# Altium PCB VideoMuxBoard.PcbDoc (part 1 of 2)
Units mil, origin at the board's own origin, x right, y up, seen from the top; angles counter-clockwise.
Board outline 4724.41 x 4724.41 mil, 4 copper layers (Top Layer, Ground, MidLayer1, Bottom Layer); 247 components, 183 nets, 999 pads, 433 vias.
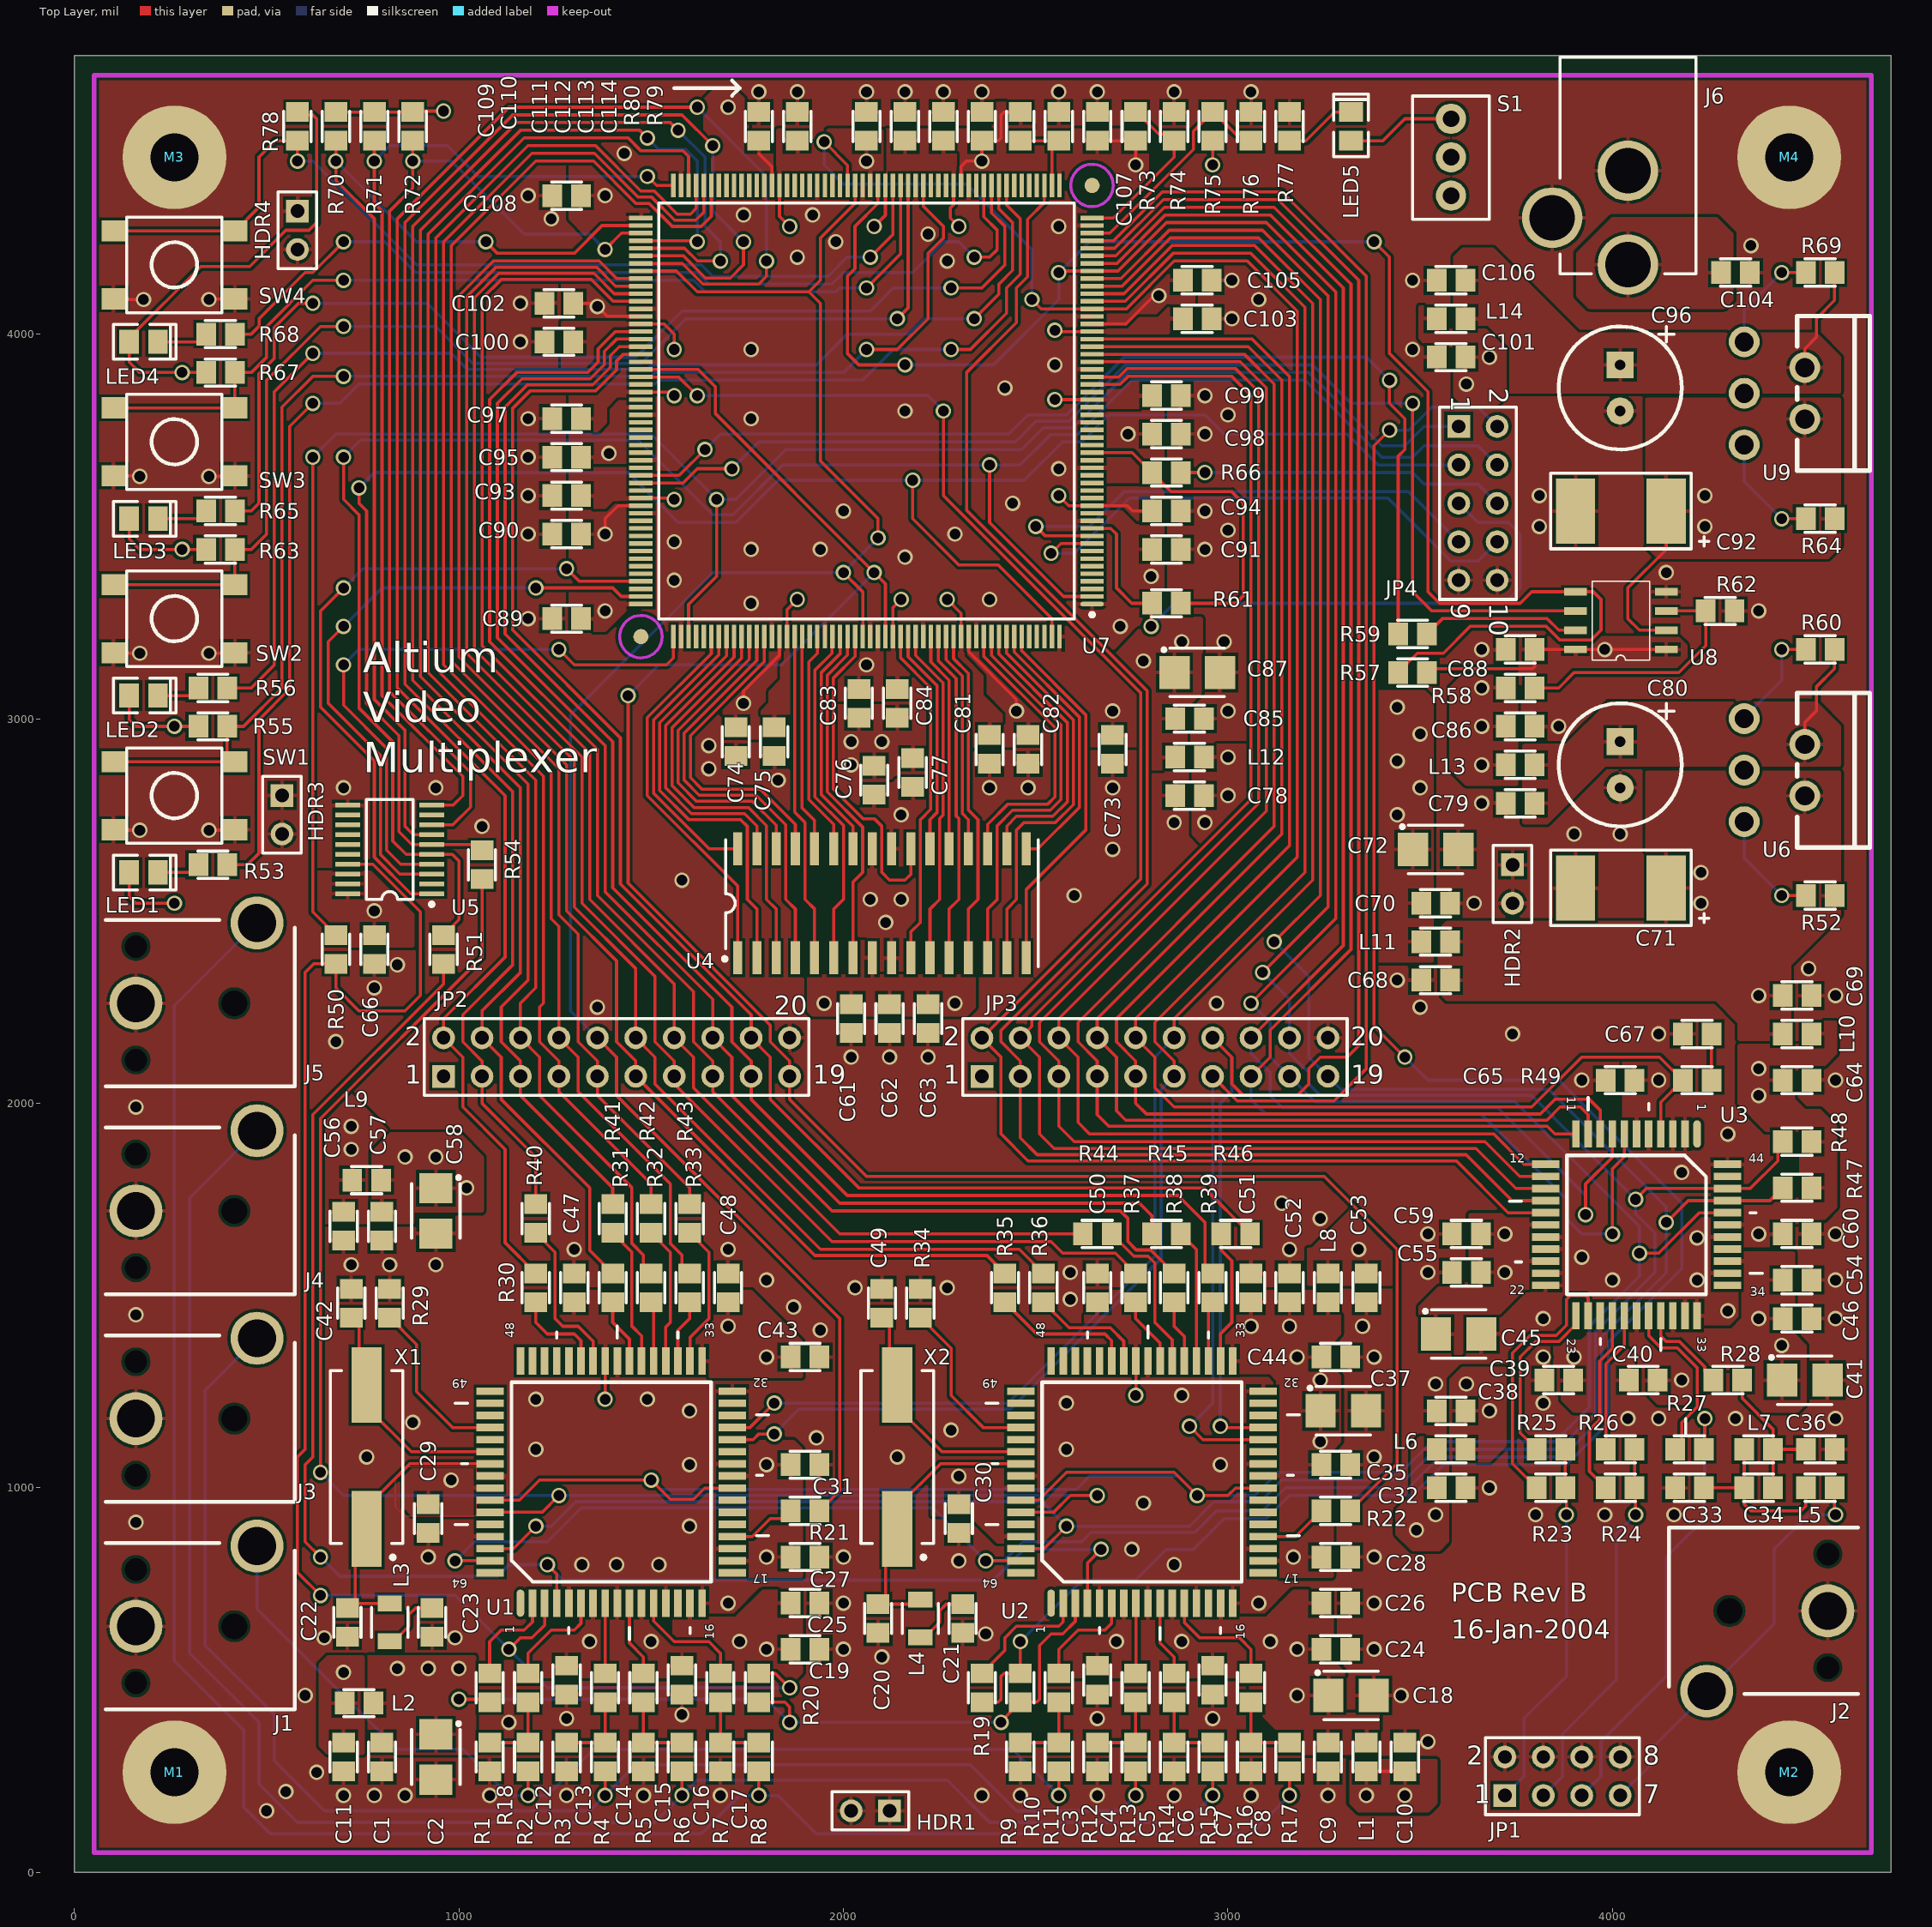
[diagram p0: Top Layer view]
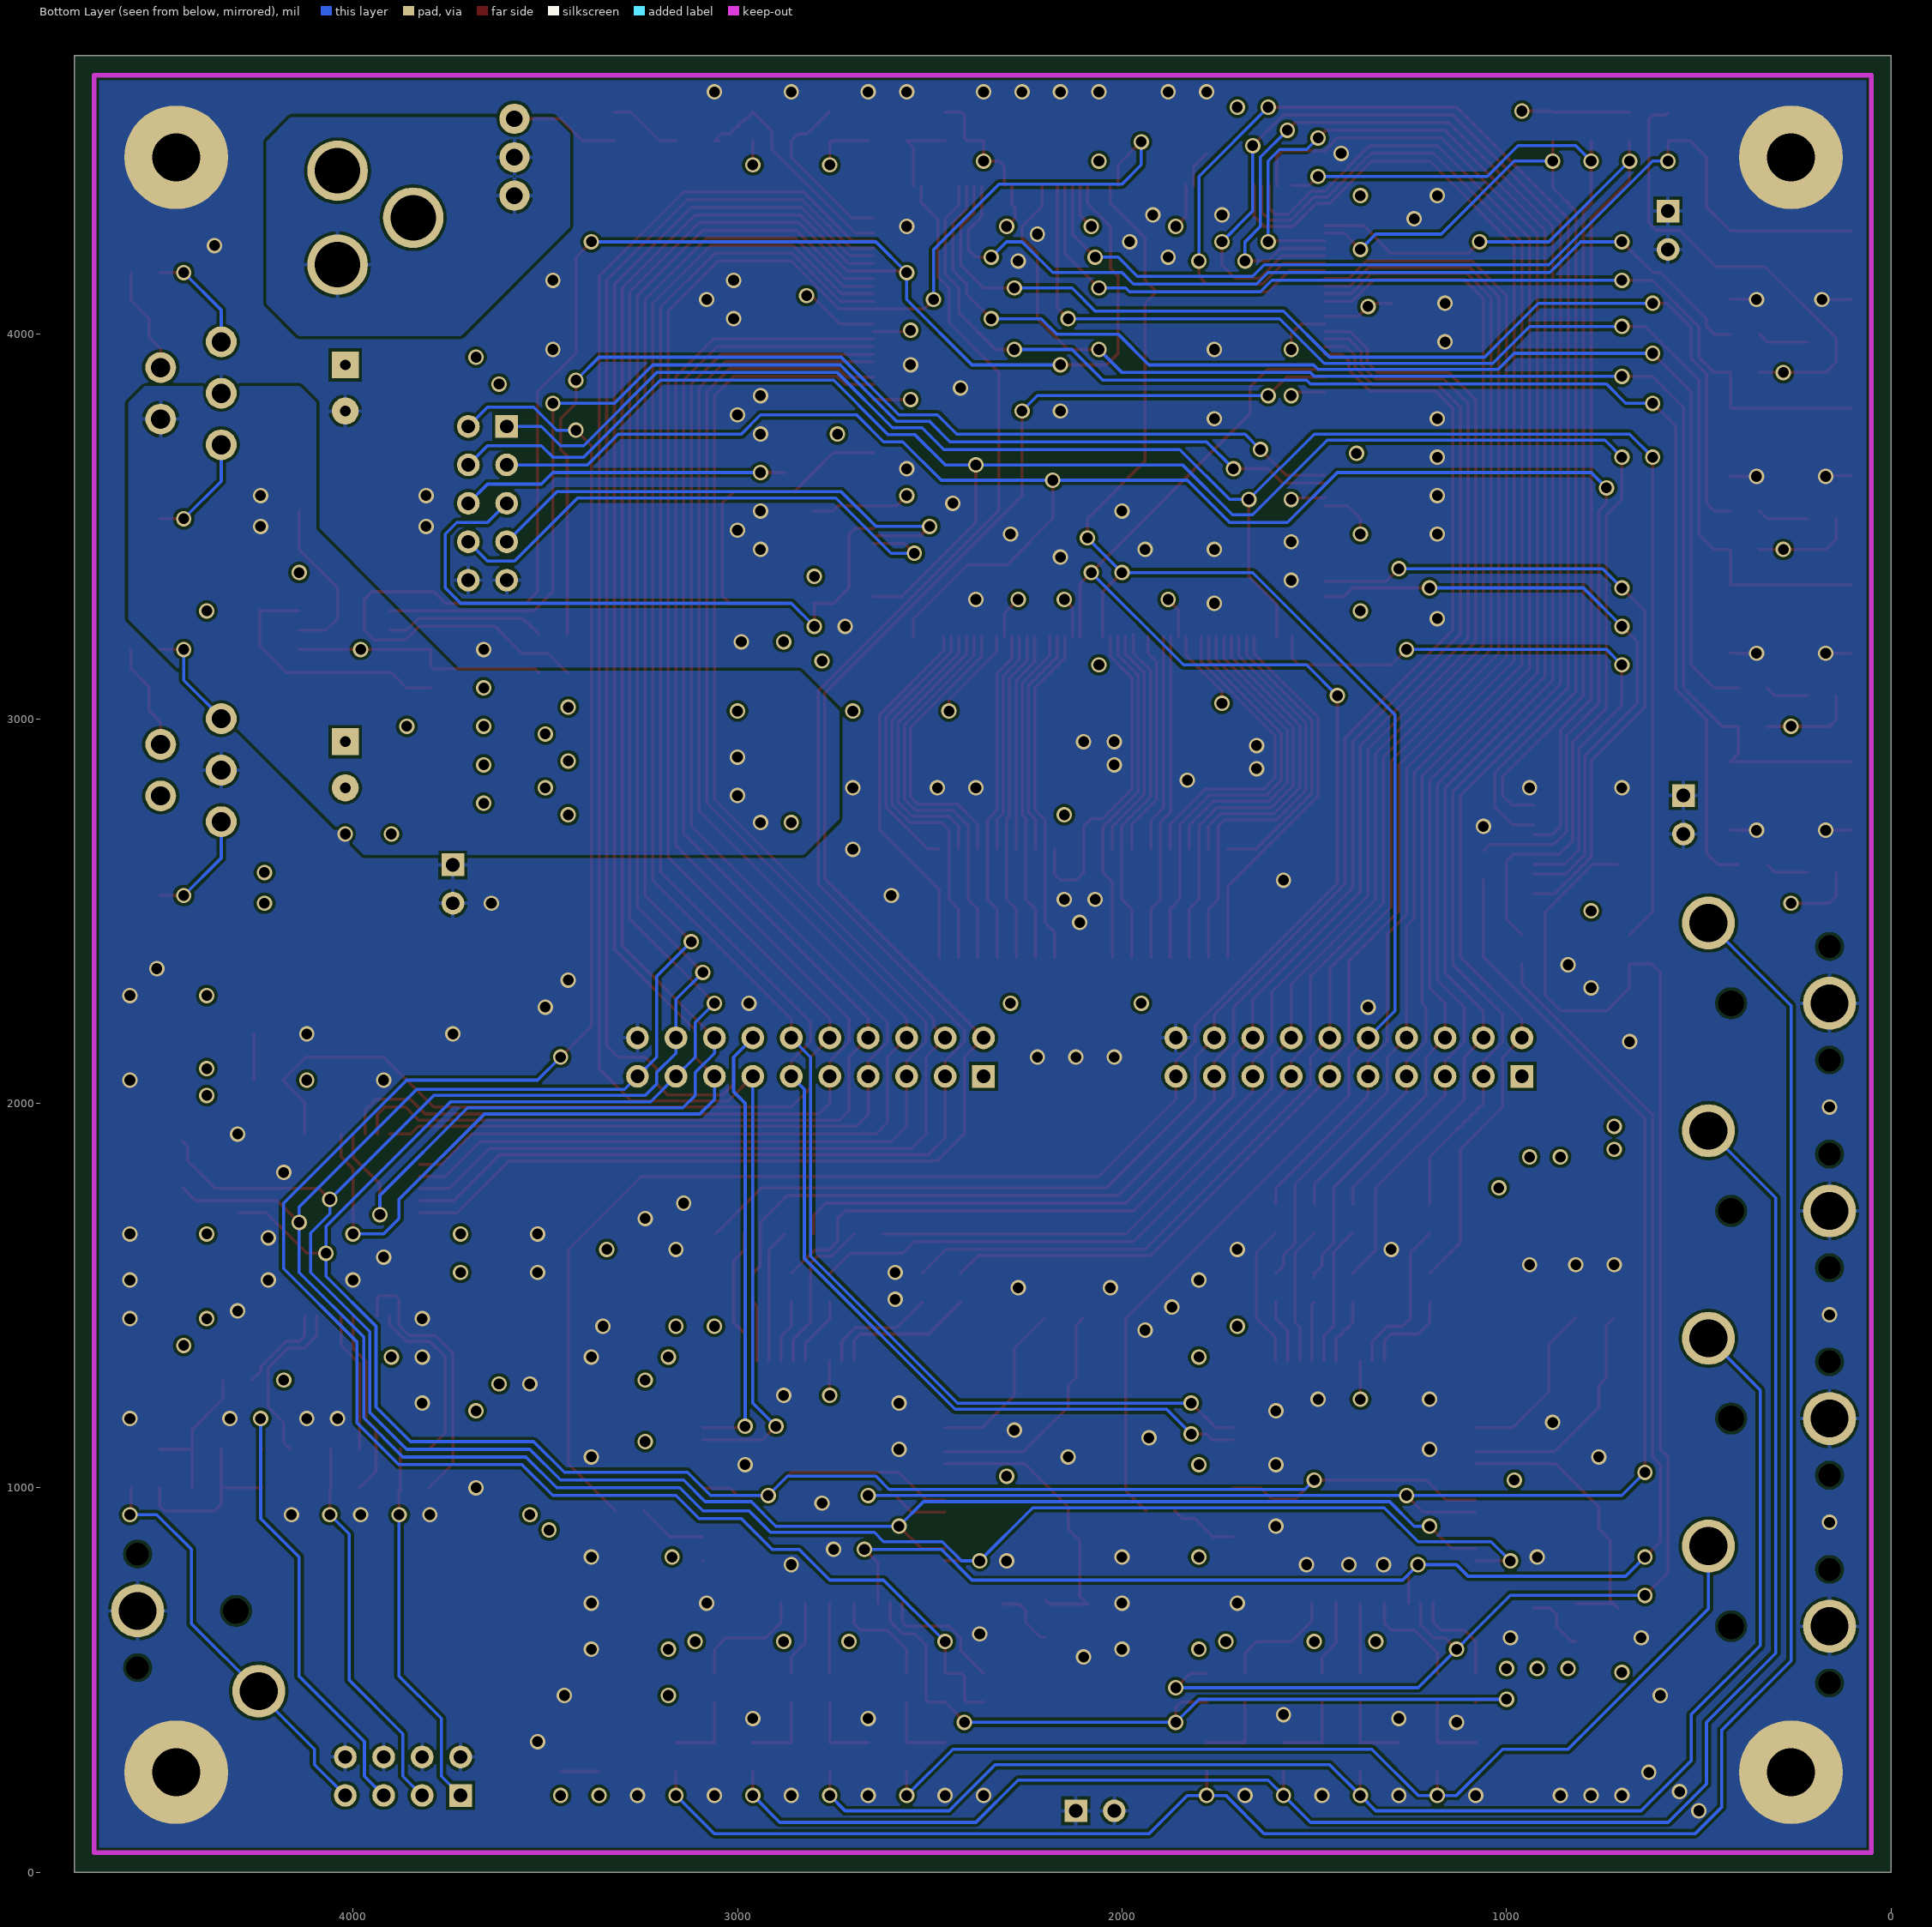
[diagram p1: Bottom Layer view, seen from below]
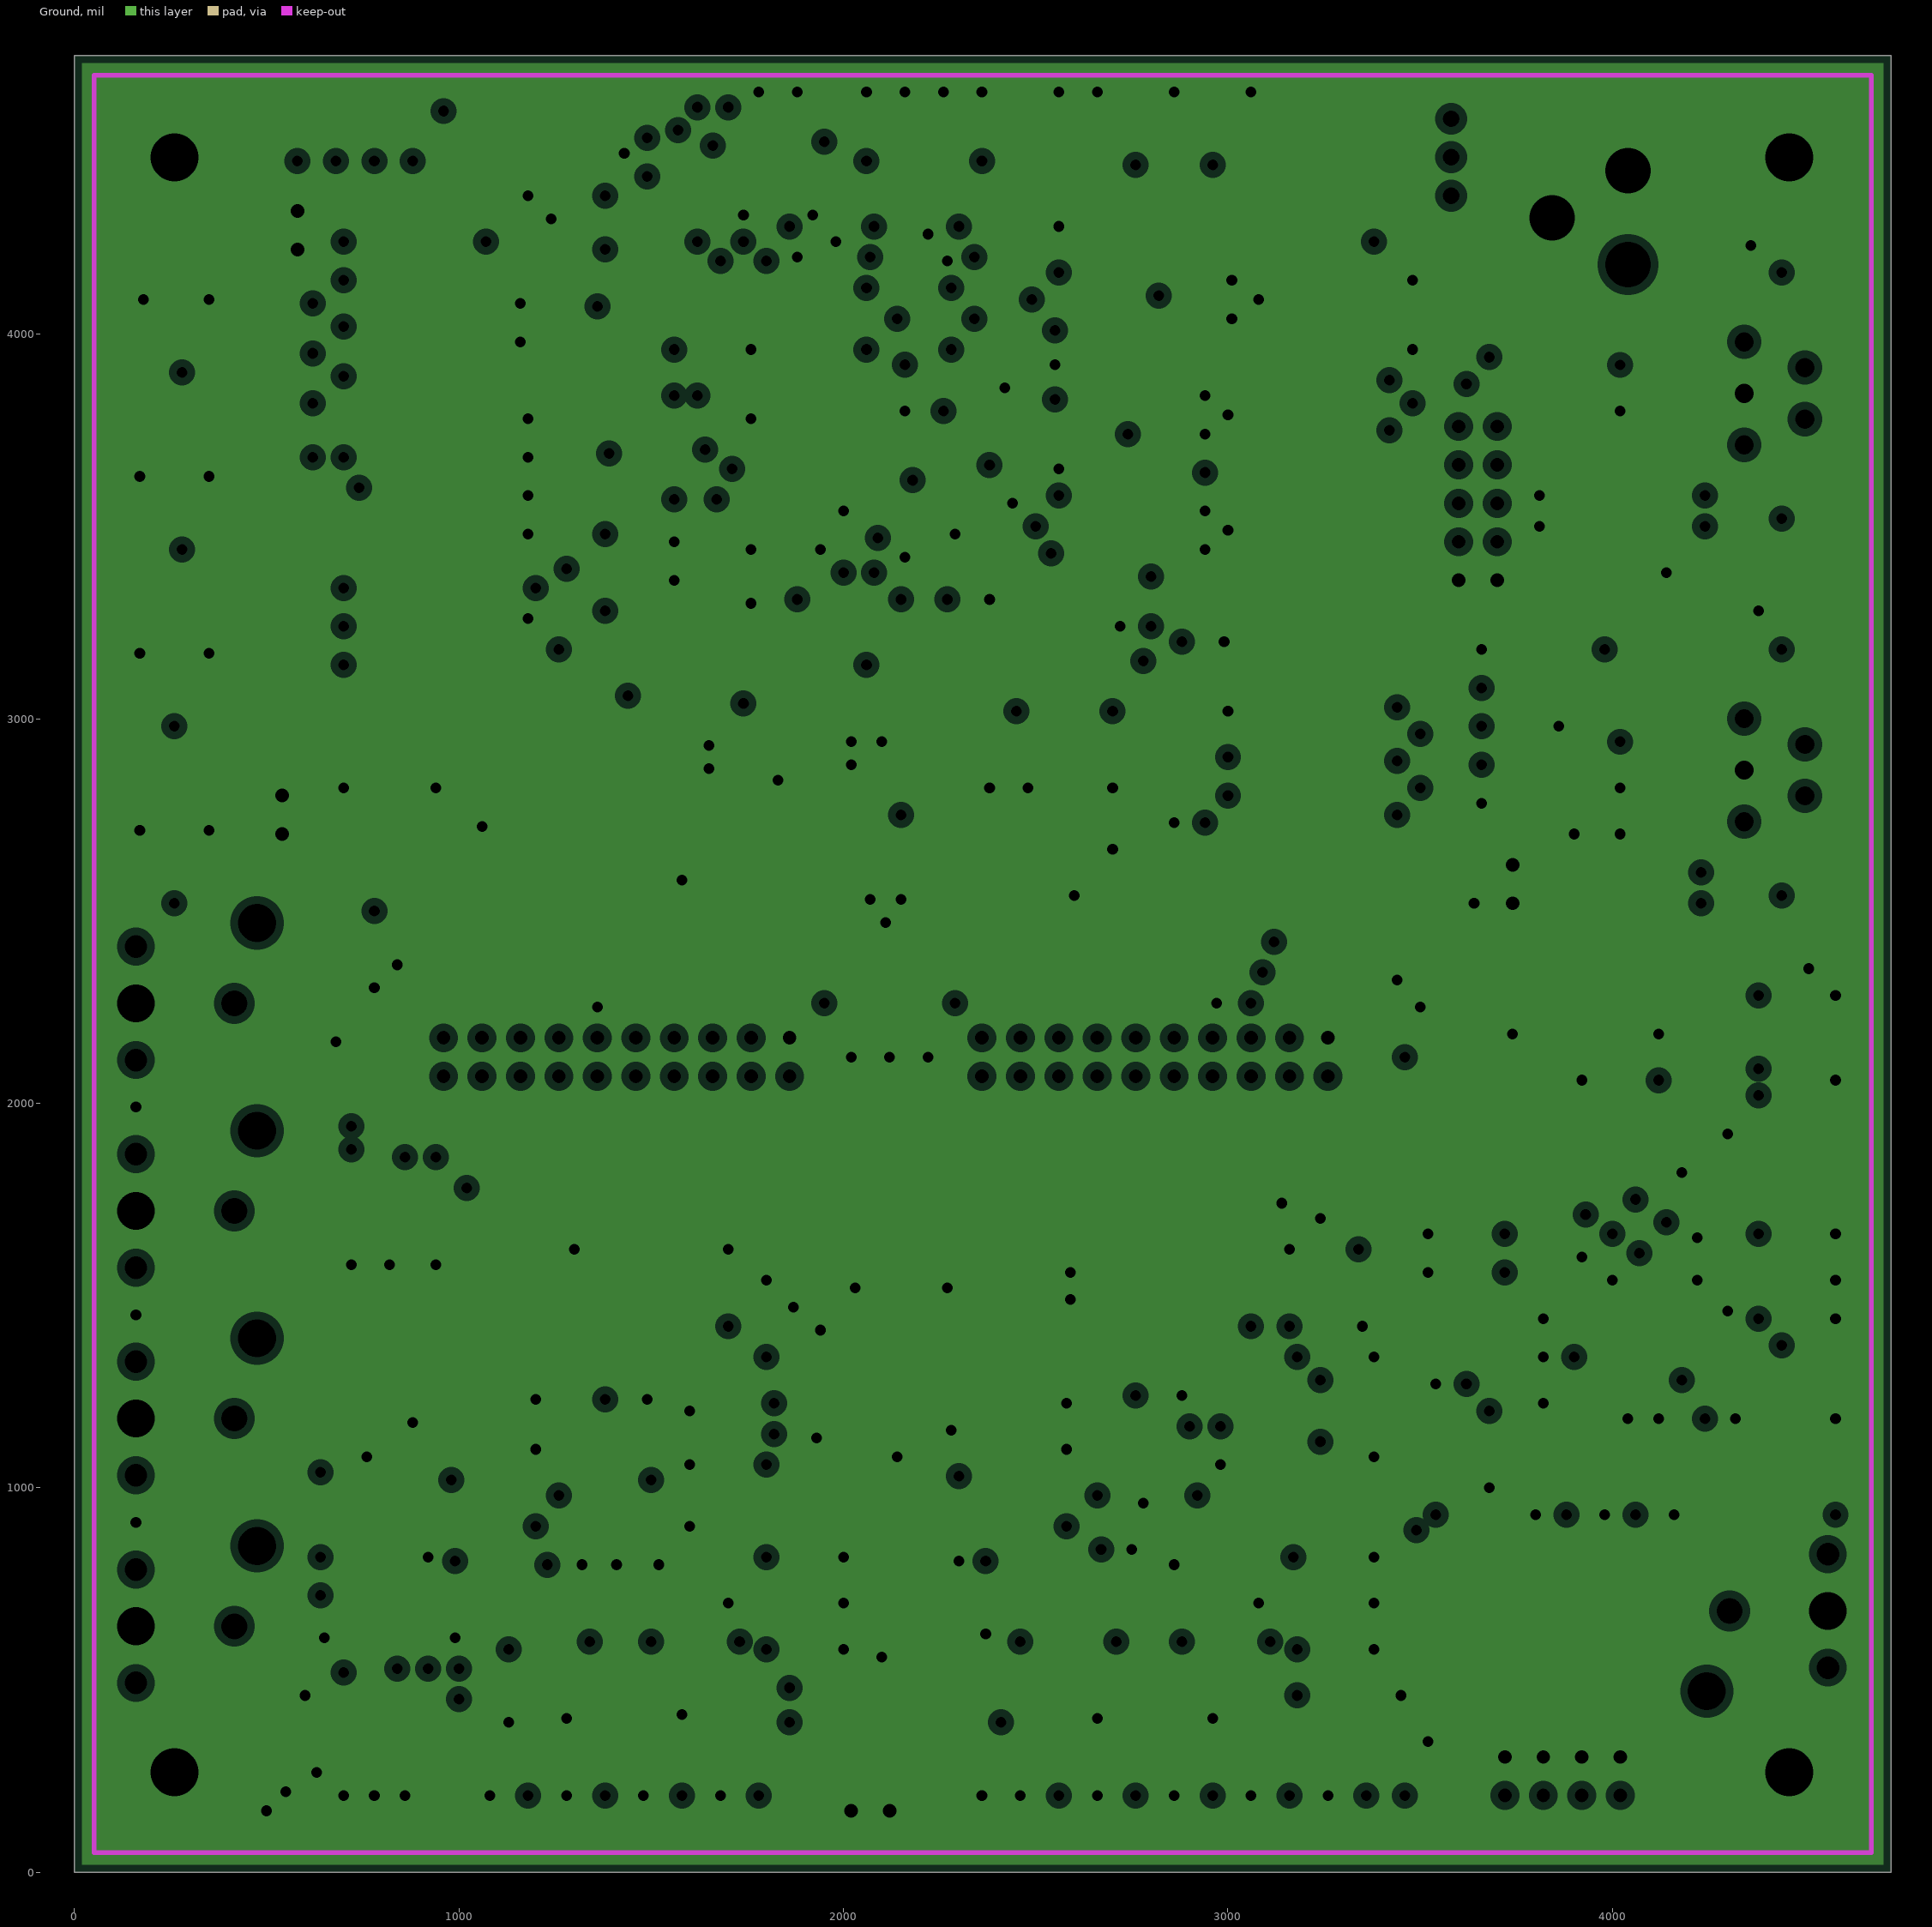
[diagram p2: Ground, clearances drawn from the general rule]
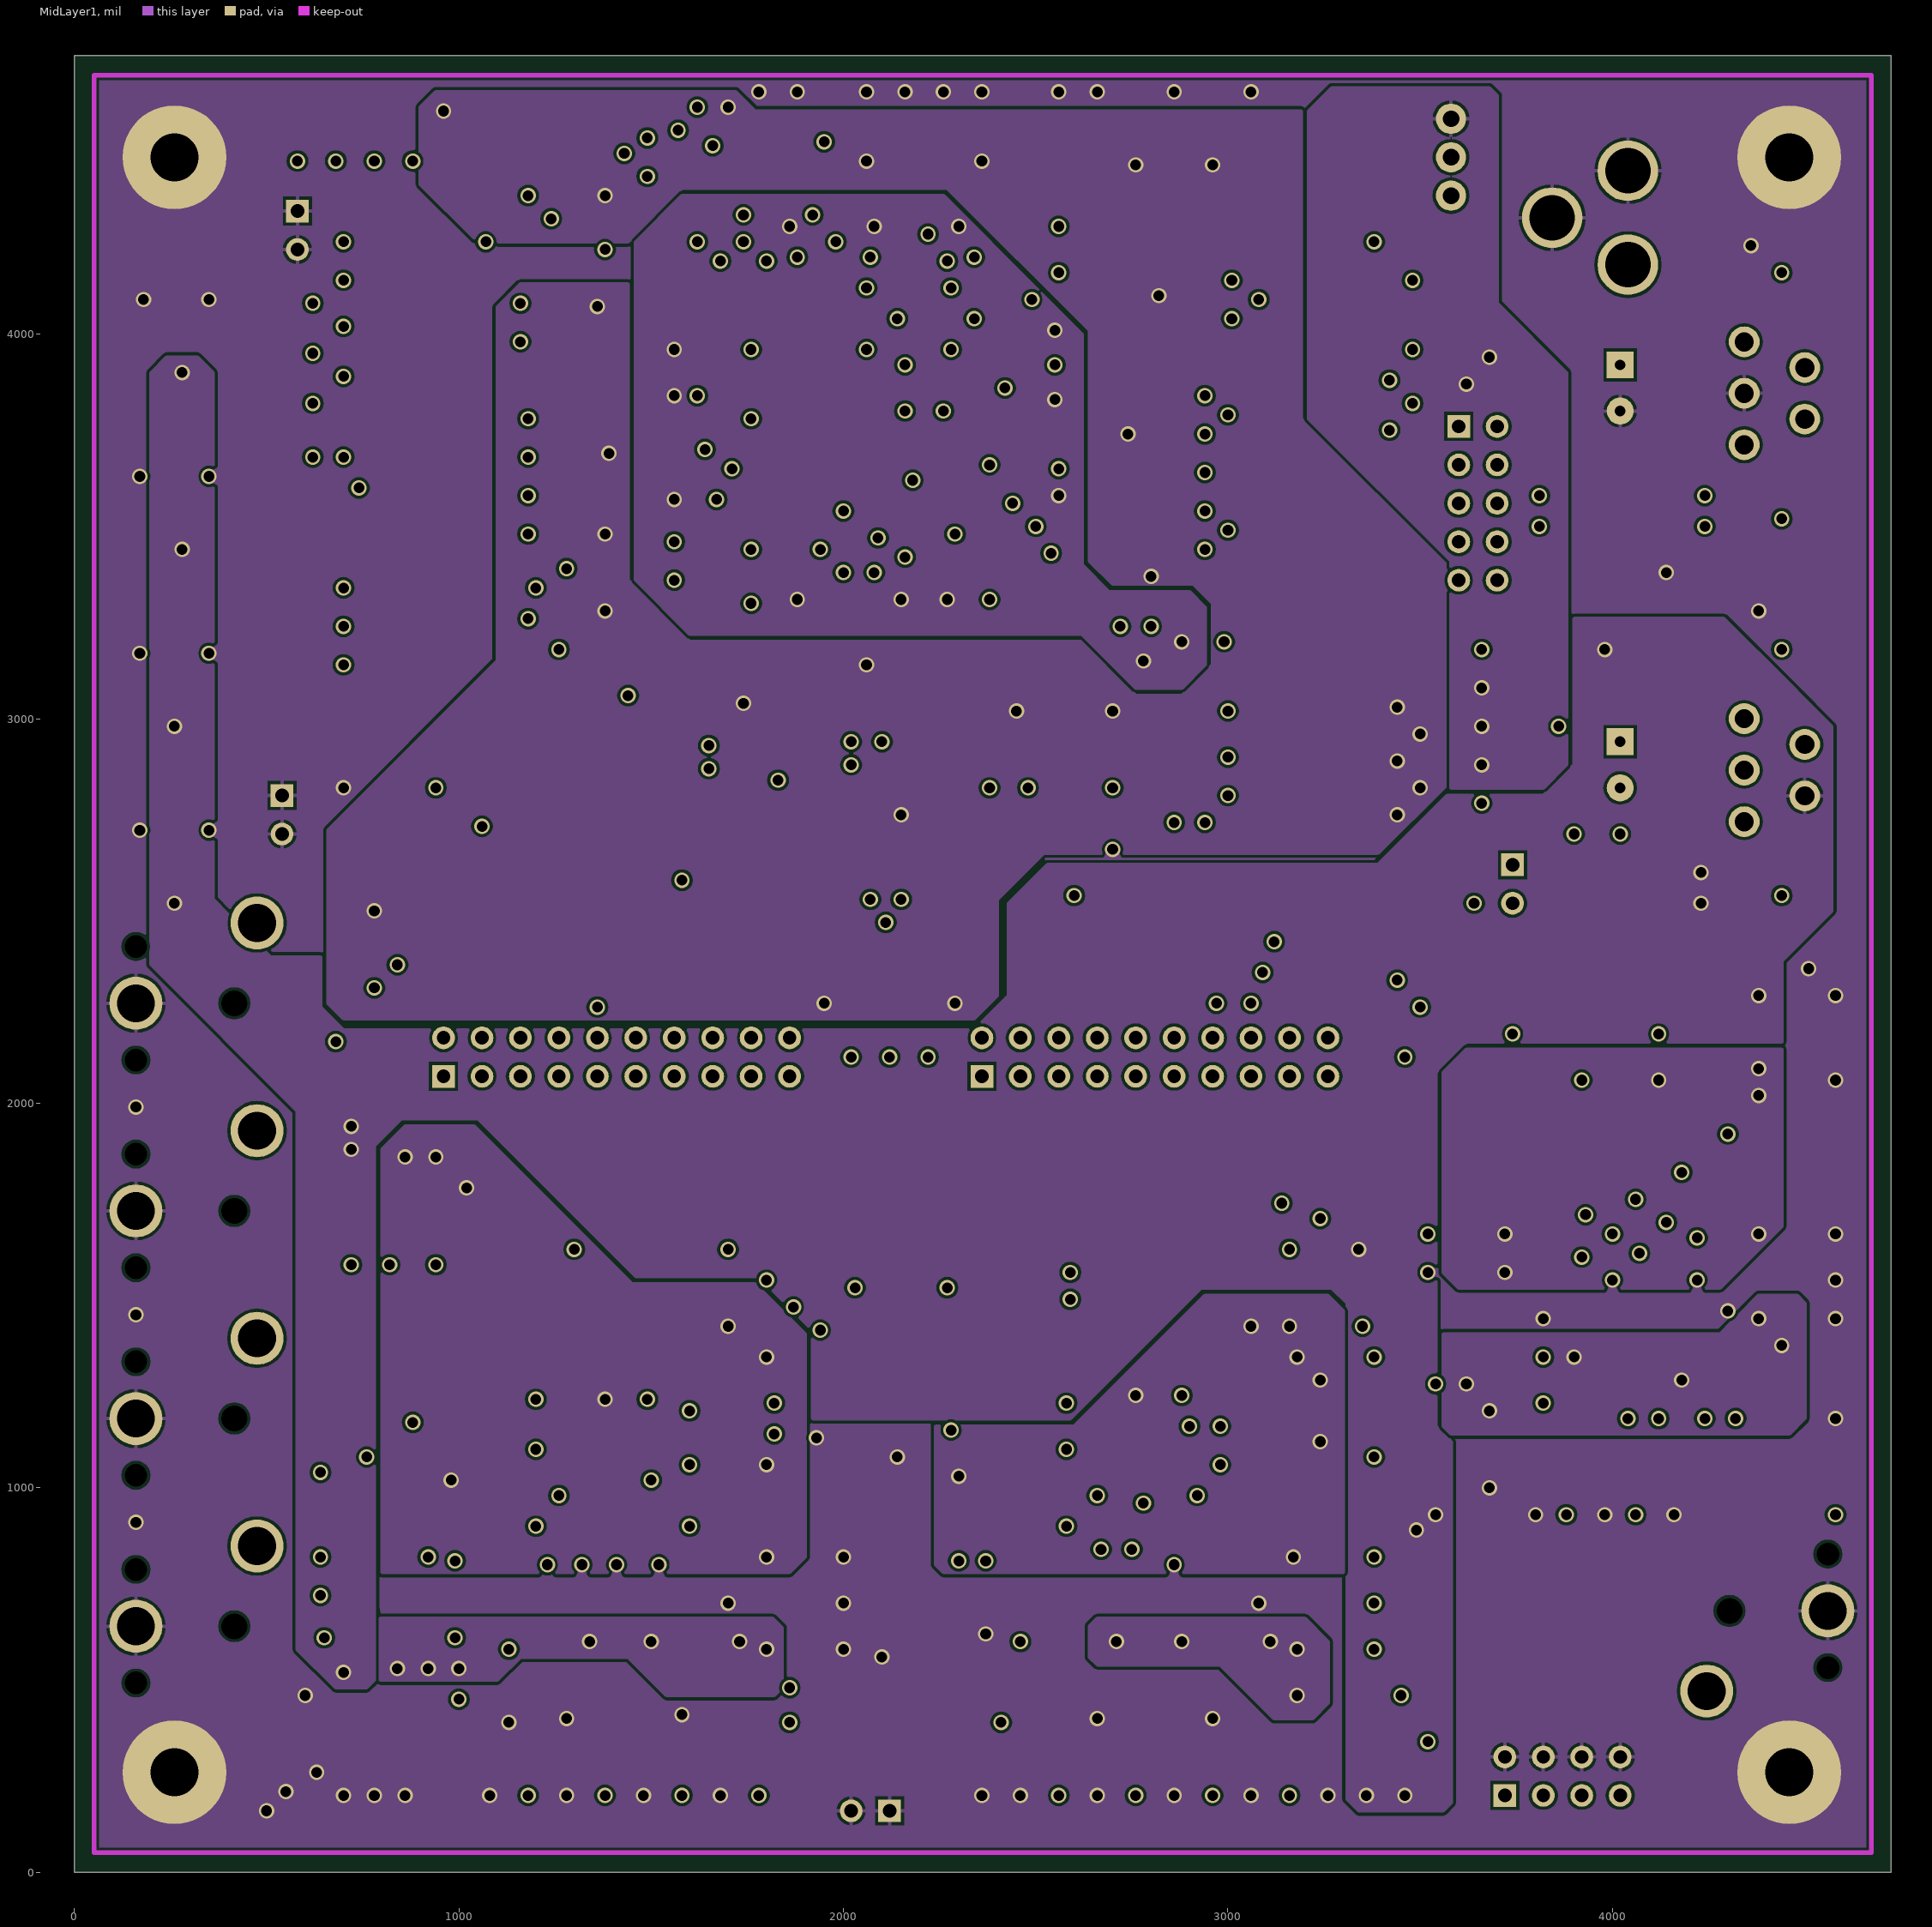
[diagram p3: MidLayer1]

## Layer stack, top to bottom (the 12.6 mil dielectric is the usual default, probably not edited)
Top Layer: signal copper 1.4
Dielectric: core 12.6, FR-4, Dk 4.8
Ground: plane copper 1.4, net GND
Dielectric: prepreg 12.6, FR-4, Dk 4.8
MidLayer1: signal copper 1.4
Dielectric: core 12.6, FR-4, Dk 4.8
Bottom Layer: signal copper 1.4

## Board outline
0,0 4724.41,0 4724.41,4724.41 0,4724.41

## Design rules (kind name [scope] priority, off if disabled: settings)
Clearance [All] p1: gap=7.87
FabricationTestPointUsage TestPointUsage [All] p1: valid=0 allowmultiple=FALSE
FabricationTestpoint Testpoint [All] p1: side=3 testpointundercomponent=TRUE minsize=40 maxsize=100 preferedsize=60 minholesize=0 maxholesize=40 preferedholesize=32 testpointgrid=1 allowsidetop=TRUE allowsidebottom=TRUE usegrid=TRUE gridtolerance=0.01
HoleSize [All] p1: absolutevalues=TRUE maxlimit=150 minlimit=24 maxpercent=80.000 minpercent=20.000
PlaneClearance [All] p1: clearance=20
PlaneConnect M3PlaneConnect [(HasFootprint('SCREW M3') AND InNet('GND'))] p1: planeconnectstyle=Direct reliefexpansion=20 reliefentries=4 reliefconductorwidth=10 reliefairgap=10 // Require no thermal relief on M3 screw holes.
PlaneConnect [All] p2: planeconnectstyle=Relief reliefexpansion=20 reliefentries=4 reliefconductorwidth=10 reliefairgap=10
PolygonConnect M3PolygonConnect [(HasFootprint('SCREW M3') AND InNet('GND'))] p1: connectstyle=Direct reliefconductorwidth=10 reliefentries=4 polygonreliefangle="90 Angle" // Require no thermal relief on M3 screw holes.
PolygonConnect [All] p2: connectstyle=Relief reliefconductorwidth=10 reliefentries=4 polygonreliefangle="90 Angle"
RoutingLayers [All] p1: top layer_v5=TRUE mid layer 1_v5=FALSE bottom layer_v5=TRUE
RoutingVias [All] p1: holewidth=24 width=40 viastyle="Through Hole" minholewidth=24 minwidth=40 maxholewidth=44 maxwidth=60
SilkscreenOverComponentPads [All] p1: minsilkscreentomaskgap=10
SolderMaskExpansion [All] p1: expansion=2
Width [All] p1: maxlimit=100 minlimit=7.87 preferedwidth=8 midlayer1_maxwidth=24
21 further rules are at their usual default settings.

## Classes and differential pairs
component class U_PCB_Controller: C61 C62 C63 C66 C68 C70 C72 C73 C74 C75 C76 C77 C78 C81 C82 C83 C84 C85 C87 C89 C90 C91 C93 C94 C95 C97 C98 C99 C100 C102 C103 C105 C107 C108 C109 C110 C111 C112 C113 C114 L11 L12 R50 R61 R70 R71 R72 R73 R74 R75 R76 R79 R80 U4 U5 U7
component class U_PCB_DecoderA: C1 C2 C11 C12 C13 C14 C15 C16 C17 C19 C22 C23 C25 C27 C29 C31 C42 C43 C47 C48 C56 C57 C58 L2 L3 L9 R1 R2 R3 R4 R5 R6 R7 R8 R18 R20 R21 R29 R30 R31 R32 R33 R40 R41 R42 R43 U1 X1
component class U_PCB_DecoderB: C3 C4 C5 C6 C7 C8 C9 C10 C18 C20 C21 C24 C26 C28 C30 C35 C37 C44 C49 C50 C51 C52 C53 L1 L4 L8 R9 R10 R11 R12 R13 R14 R15 R16 R17 R19 R22 R34 R35 R36 R37 R38 R39 R44 R45 R46 U2 X2
component class U_PCB_Encoder: C32 C33 C34 C36 C38 C39 C40 C41 C45 C46 C54 C55 C59 C60 C64 C65 C67 C69 J2 JP1 L5 L6 L7 L10 R23 R24 R25 R26 R27 R28 R47 R48 R49 U3
component class U_PCB_Headers: JP2 JP3 JP4 R66
component class U_PCB_IO: J1 J3 J4 J5 LED1 LED2 LED3 LED4 LED5 R53 R55 R56 R63 R65 R67 R68 R77 R78 SW1 SW2 SW3 SW4
component class U_PCB_Power: C71 C79 C80 C86 C88 C92 C96 C101 C104 C106 HDR1 HDR2 HDR3 HDR4 J6 L13 L14 R52 R57 R58 R59 R60 R62 R64 R69 S1 U6 U8 U9
net class A[16..0]: A0 A1 A2 A3 A4 A5 A6 A7 A8 A9 A10 A11 A12 A13 A14 A15 A16
net class D[7..0]: D0 D1 D2 D3 D4 D5 D6 D7
net class KEY[3..0]: KEY0 KEY1 KEY2 KEY3
net class LED[3..0]: LED0 LED3 LED4 LED5
net class MP[7..0]: MPOUT0 MPOUT1 MPOUT2 MPOUT3 MPOUT4 MPOUT5 MPOUT6 MPOUT7
component class PCB_Top: R51 R54

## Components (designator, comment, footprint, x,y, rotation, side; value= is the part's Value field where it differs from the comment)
C1 "0.1uF" CC2012-0805 800,300 r270 top (schematic designator C54)
C2 "10uF" MCCT-B 940,300 r270 top (schematic designator C56)
C3 "22nF" CC2012-0805 2560,480 r90 top (schematic designator C86)
C4 "10nF" CC2012-0805 2660,500 r90 top (schematic designator C73)
C5 "22nF" CC2012-0805 2760,480 r90 top (schematic designator C85)
C6 "22nF" CC2012-0805 2860,480 r90 top (schematic designator C84)
C7 "10nF" CC2012-0805 2960,500 r90 top (schematic designator C74)
C8 "22nF" CC2012-0805 3060,480 r90 top (schematic designator C83)
C9 "0.1uF" CC2012-0805 3260,300 r270 top (schematic designator C77)
C10 "1nF" CC2012-0805 3460,300 r90 top (schematic designator C67)
C11 "1nF" CC2012-0805 700,300 r270 top (schematic designator C44)
C12 "22nF" CC2012-0805 1180,480 r90 top (schematic designator C63)
C13 "10nF" CC2012-0805 1280,500 r90 top (schematic designator C50)
C14 "22nF" CC2012-0805 1380,480 r90 top (schematic designator C62)
C15 "22nF" CC2012-0805 1480,480 r90 top (schematic designator C61)
C16 "10nF" CC2012-0805 1580,500 r90 top (schematic designator C51)
C17 "22nF" CC2012-0805 1680,480 r90 top (schematic designator C60)
C18 "10uF" MCCT-B 3320,460 r0 top (schematic designator C79)
C19 "1nF" CC2012-0805 1900,580 r180 top (schematic designator C43)
C20 "10pF" CC2012-0805 2090,660 r90 top (schematic designator C81)
C21 "1nF" CC2012-0805 2310,660 r90 top (schematic designator C64)
C22 "10pF" CC2012-0805 710,650 r90 top (schematic designator C58)
C23 "1nF" CC2012-0805 930,650 r90 top (schematic designator C41)
C24 "1nF" CC2012-0805 3280,580 r180 top (schematic designator C66)
C25 "1nF" CC2012-0805 1900,700 r180 top (schematic designator C42)
C26 "1nF" CC2012-0805 3280,700 r180 top (schematic designator C65)
C27 "10nF" CC2012-0805 1900,820 r0 top (schematic designator C53)
C28 "10nF" CC2012-0805 3280,820 r0 top (schematic designator C76)
C29 "100nF" CC2012-0805 920,920 r270 top (schematic designator C47)
C30 "100nF" CC2012-0805 2300,920 r270 top (schematic designator C70)
C31 "1nF" CC2012-0805 1900,1060 r0 top (schematic designator C49)
C32 "1nF" CC2012-0805 3580,1000 r0 top (schematic designator C90)
C33 "470pF" CC2012-0805 4200,1000 r180 top (schematic designator C102)
C34 "100pF" CC2012-0805 4380,1000 r180 top (schematic designator C104)
C35 "1nF" CC2012-0805 3280,1060 r0 top (schematic designator C72)
C36 "330pF" CC2012-0805 4540,1100 r0 top (schematic designator C103)
C37 "10uF" MCCT-B 3300,1200 r0 top (schematic designator C80)
C38 "0.1uF" CC2012-0805 3580,1200 r180 top (schematic designator C99)
C39 "1nF" CC2012-0805 3860,1280 r180 top (schematic designator C92)
C40 "10nF" CC2012-0805 4080,1280 r180 top (schematic designator C97)
C41 "10uF" MCCT-B 4500,1280 r0 top (schematic designator C101)
C42 "10pF" CC2012-0805 720,1480 r90 top (schematic designator C59)
C43 "1nF" CC2012-0805 1900,1340 r0 top (schematic designator C45)
C44 "1nF" CC2012-0805 3280,1340 r0 top (schematic designator C68)
C45 "10uF" MCCT-B 3600,1400 r0 top (schematic designator C100)
C46 "10nF" CC2012-0805 4480,1440 r0 top (schematic designator C96)
C47 "1nF" CC2012-0805 1300,1520 r90 top (schematic designator C48)
C48 "10nF" CC2012-0805 1700,1520 r90 top (schematic designator C52)
C49 "10pF" CC2012-0805 2100,1480 r90 top (schematic designator C82)
C50 "1nF" CC2012-0805 2660,1520 r90 top (schematic designator C71)
C51 "10nF" CC2012-0805 3060,1520 r90 top (schematic designator C75)
C52 "0.1uF" CC2012-0805 3160,1520 r90 top (schematic designator C78)
C53 "1nF" CC2012-0805 3360,1520 r270 top (schematic designator C69)
C54 "1nF" CC2012-0805 4480,1540 r0 top (schematic designator C91)
C55 "10nF" CC2012-0805 3620,1560 r0 top (schematic designator C94)
C56 "1nF" CC2012-0805 700,1680 r270 top (schematic designator C46)
C57 "0.1uF" CC2012-0805 800,1680 r270 top (schematic designator C55)
C58 "10uF" MCCT-B 940,1720 r270 top (schematic designator C57)
C59 "1nF" CC2012-0805 3620,1660 r0 top (schematic designator C88)
C60 "10nF" CC2012-0805 4480,1660 r180 top (schematic designator C95)
C61 "0.1uF" CC2012-0805 2020,2220 r270 top (schematic designator C32)
C62 "1nF" CC2012-0805 2120,2220 r270 top (schematic designator C2)
C63 "10nF" CC2012-0805 2220,2220 r270 top (schematic designator C22)
C64 "0.1uF" CC2012-0805 4480,2060 r0 top (schematic designator C98)
C65 "1nF" CC2012-0805 4020,2060 r0 top (schematic designator C87)
C66 "10nF" CC2012-0805 780,2400 r270 top (schematic designator C27)
C67 "10nF" CC2012-0805 4220,2180 r180 top (schematic designator C93)
C68 "1nF" CC2012-0805 3540,2320 r180 top (schematic designator C20)
C69 "1nF" CC2012-0805 4480,2280 r0 top (schematic designator C89)
C70 "0.1uF" CC2012-0805 3540,2520 r0 top (schematic designator C38)
C71 "47uF" MCCTD 4140,2560 r180 top (schematic designator C113)
C72 "10uF" MCCT-B 3540,2660 r0 top (schematic designator C40)
C73 "10nF" CC2012-0805 2700,2920 r270 top (schematic designator C24)
C74 "1nF" CC2012-0805 1720,2940 r270 top (schematic designator C5)
C75 "1nF" CC2012-0805 1820,2940 r270 top (schematic designator C15)
C76 "1nF" CC2012-0805 2080,2840 r90 top (schematic designator C1)
C77 "10nF" CC2012-0805 2180,2860 r90 top (schematic designator C21)
C78 "1nF" CC2012-0805 2900,2800 r180 top (schematic designator C19)
C79 "0.1uF" CC2012-0805 3760,2780 r180 top (schematic designator C109)
C80 "470uF 16V" RB8/3.5 4020,2880 r0 top (schematic designator C111)
C81 "10nF" CC2012-0805 2380,2920 r90 top (schematic designator C30)
C82 "1nF" CC2012-0805 2480,2920 r270 top (schematic designator C7)
C83 "10nF" CC2012-0805 2040,3040 r270 top (schematic designator C25)
C84 "0.1uF" CC2012-0805 2140,3040 r270 top (schematic designator C35)
C85 "0.1uF" CC2012-0805 2900,3000 r0 top (schematic designator C36)
C86 "1nF" CC2012-0805 3760,2980 r0 top (schematic designator C105)
C87 "10uF" MCCT-B 2920,3120 r0 top (schematic designator C39)
C88 "10nF" CC2012-0805 3760,3180 r180 top (schematic designator C108)
C89 "1nF" CC2012-0805 1280,3260 r180 top (schematic designator C4)
C90 "1nF" CC2012-0805 1280,3480 r180 top (schematic designator C12)
C91 "0.1uF" CC2012-0805 2840,3440 r0 top (schematic designator C34)
C92 "47uF" MCCTD 4140,3540 r180 top (schematic designator C114)
C93 "1nF" CC2012-0805 1280,3580 r180 top (schematic designator C14)
C94 "1nF" CC2012-0805 2840,3540 r0 top (schematic designator C16)
C95 "1nF" CC2012-0805 1280,3680 r180 top (schematic designator C11)
C96 "470uF 16V" RB8/3.5 4020,3860 r0 top (schematic designator C112)
C97 "10nF" CC2012-0805 1280,3780 r0 top (schematic designator C29)
C98 "1nF" CC2012-0805 2840,3740 r0 top (schematic designator C3)
C99 "10nF" CC2012-0805 2840,3840 r180 top (schematic designator C31)
C100 "1nF" CC2012-0805 1260,3980 r180 top (schematic designator C18)
C101 "1nF" CC2012-0805 3580,3940 r180 top (schematic designator C107)
C102 "1nF" CC2012-0805 1260,4080 r180 top (schematic designator C10)
C103 "1nF" CC2012-0805 2920,4040 r0 top (schematic designator C17)
C104 "1nF" CC2012-0805 4320,4160 r0 top (schematic designator C106)
C105 "10nF" CC2012-0805 2920,4140 r0 top (schematic designator C23)
C106 "0.1uF" CC2012-0805 3580,4140 r180 top (schematic designator C110)
C107 "1nF" CC2012-0805 2660,4540 r90 top (schematic designator C8)
C108 "10nF" CC2012-0805 1280,4360 r180 top (schematic designator C26)
C109 "0.1uF" CC2012-0805 1780,4540 r90 top (schematic designator C33)
C110 "10nF" CC2012-0805 1880,4540 r270 top (schematic designator C28)
C111 "1nF" CC2012-0805 2060,4540 r90 top (schematic designator C6)
C112 "0.1uF" CC2012-0805 2160,4540 r270 top (schematic designator C37)
C113 "1nF" CC2012-0805 2260,4540 r90 top (schematic designator C13)
C114 "1nF" CC2012-0805 2360,4540 r90 top (schematic designator C9)
HDR1 "Header 2" HDR1X2 2120,160 r180 top (schematic designator HDR3)
HDR2 "Header 2" HDR1X2 3740,2620 r270 top (schematic designator HDR1)
HDR3 "Header 2" HDR1X2 540,2800 r270 top (schematic designator HDR2)
HDR4 "Header 2" HDR1X2 580,4320 r270 top
J1 "RCA" RCA_MR551L 160,640 r0 top (schematic designator J5)
J2 "RCA" RCA_MR551L 4560,680 r180 top (schematic designator J1)
J3 "RCA" RCA_MR551L 160,1180 r0 top (schematic designator J4)
J4 "RCA" RCA_MR551L 160,1720 r0 top (schematic designator J3)
J5 "RCA" RCA_MR551L 160,2260 r0 top (schematic designator J2)
J6 "PWR2.5" PWR2.5 4040,4720 r270 top
JP1 "Header 4X2" HDR2X4 3720,200 r0 top
JP2 "Header 10X2" HDR2X10 960,2070 r0 top (schematic designator JP3)
JP3 "Header 10X2" HDR2X10 2360,2070 r0 top (schematic designator JP4)
JP4 "Header 5X2" HDR2X5 3600,3760 r270 top (schematic designator JP2)
L1 "300R" CC2012-0805 3360,300 r90 top (schematic designator L7)
L2 "300R" CC2012-0805 740,440 r0 top (schematic designator L4)
L3 "Inductor" SIMID1008-A 820,650 r90 top
L4 "Inductor" SIMID1008-A 2200,660 r90 top (schematic designator L6)
L5 "Inductor" CC2012-0805 4540,1000 r0 top (schematic designator L10)
L6 "300R" CC2012-0805 3580,1100 r0 top (schematic designator L13)
L7 "Inductor" CC2012-0805 4380,1100 r180 top (schematic designator L9)
L8 "300R" CC2012-0805 3260,1520 r270 top
L9 "300R" CC2012-0805 760,1800 r0 top (schematic designator L5)
L10 "300R" CC2012-0805 4480,2180 r0 top (schematic designator L12)
L11 "60R" CC2012-0805 3540,2420 r180 top (schematic designator L2)
L12 "60R" CC2012-0805 2900,2900 r180 top (schematic designator L1)
L13 "60R" CC2012-0805 3760,2880 r0 top (schematic designator L14)
L14 "60R" CC2012-0805 3580,4040 r0 top (schematic designator L15)
LED1 "HSMX-C670" "SMD _LED" 180,2600 r180 top (schematic designator LED5)
LED2 "HSMX-C670" "SMD _LED" 180,3060 r180 top (schematic designator LED4)
LED3 "HSMX-C670" "SMD _LED" 180,3520 r180 top
LED4 "HSMX-C670" "SMD _LED" 180,3980 r180 top (schematic designator LED2)
LED5 "HSMX-C670" "SMD _LED" 3320,4540 r270 top (schematic designator LED1)
M1 "Comment" "SCREW M3" 260,260 r0 top
M2 "Comment" "SCREW M3" 4460,260 r0 top
M3 "Comment" "SCREW M3" 260,4460 r0 top
M4 "Comment" "SCREW M3" 4460,4460 r0 top
R1 "100" CC2012-0805 1080,300 r90 top (schematic designator R24)
R2 "47" CC2012-0805 1180,300 r90 top (schematic designator R30)
R3 "100" CC2012-0805 1280,300 r90 top (schematic designator R23)
R4 "47" CC2012-0805 1380,300 r90 top (schematic designator R29)
R5 "100" CC2012-0805 1480,300 r90 top (schematic designator R21)
R6 "47" CC2012-0805 1580,300 r90 top (schematic designator R28)
R7 "100" CC2012-0805 1680,300 r90 top (schematic designator R16)
R8 "47" CC2012-0805 1780,300 r90 top (schematic designator R27)
R9 "100" CC2012-0805 2460,300 r90 top (schematic designator R43)
R10 "0" CC2012-0805 2460,480 r90 top (schematic designator R31)
R11 "47" CC2012-0805 2560,300 r90 top (schematic designator R49)
R12 "100" CC2012-0805 2660,300 r90 top (schematic designator R42)
R13 "47" CC2012-0805 2760,300 r90 top (schematic designator R48)
R14 "100" CC2012-0805 2860,300 r90 top (schematic designator R40)
R15 "47" CC2012-0805 2960,300 r90 top (schematic designator R47)
R16 "100" CC2012-0805 3060,300 r90 top (schematic designator R35)
R17 "47" CC2012-0805 3160,300 r90 top (schematic designator R46)
R18 "100" CC2012-0805 1080,480 r90 top (schematic designator R12)
R19 "100" CC2012-0805 2360,480 r90 top (schematic designator R58)
R20 "100" CC2012-0805 1780,480 r270 top (schematic designator R77)
R21 "100" CC2012-0805 1900,940 r180 top (schematic designator R25)
R22 "100" CC2012-0805 3280,940 r180 top (schematic designator R44)
R23 "10" CC2012-0805 3840,1000 r0 top (schematic designator R53)
R24 "22" CC2012-0805 4020,1000 r0 top (schematic designator R56)
R25 "22" CC2012-0805 3840,1100 r0 top (schematic designator R55)
R26 "10" CC2012-0805 4020,1100 r0 top (schematic designator R54)
R27 "22" CC2012-0805 4200,1100 r0 top (schematic designator R80)
R28 "4.7" CC2012-0805 4300,1280 r0 top (schematic designator R57)
R29 "1k" CC2012-0805 820,1480 r270 top (schematic designator R26)
R30 "100" CC2012-0805 1200,1520 r270 top (schematic designator R22)
R31 "100" CC2012-0805 1400,1520 r270 top (schematic designator R19)
R32 "100" CC2012-0805 1500,1520 r270 top (schematic designator R17)
R33 "100" CC2012-0805 1600,1520 r270 top (schematic designator R14)
R34 "1k" CC2012-0805 2200,1480 r270 top (schematic designator R45)
R35 "100" CC2012-0805 2420,1520 r270 top (schematic designator R41)
R36 "100" CC2012-0805 2520,1520 r270 top (schematic designator R39)
R37 "100" CC2012-0805 2760,1520 r270 top (schematic designator R38)
R38 "100" CC2012-0805 2860,1520 r270 top (schematic designator R36)
R39 "100" CC2012-0805 2960,1520 r270 top (schematic designator R33)
R40 "100" CC2012-0805 1200,1700 r270 top (schematic designator R20)
R41 "100" CC2012-0805 1400,1700 r270 top (schematic designator R18)
R42 "100" CC2012-0805 1500,1700 r270 top (schematic designator R15)
R43 "100" CC2012-0805 1600,1700 r270 top (schematic designator R13)
R44 "100" CC2012-0805 2660,1660 r0 top (schematic designator R37)
R45 "100" CC2012-0805 2840,1660 r0 top (schematic designator R34)
R46 "100" CC2012-0805 3020,1660 r180 top (schematic designator R32)
R47 "4K7" CC2012-0805 4480,1780 r0 top (schematic designator R50)
R48 "4K7" CC2012-0805 4480,1900 r0 top (schematic designator R51)
R49 "47" CC2012-0805 4220,2060 r0 top (schematic designator R52)
R50 "0" CC2012-0805 680,2400 r270 top (schematic designator R1)
R51 "0" CC2012-0805 960,2400 r270 top (schematic designator R79)
R52 "4k7" CC2012-0805 4540,2540 r0 top (schematic designator R70)
R53 "330" CC2012-0805 360,2620 r0 top (schematic designator R68)
R54 "0" CC2012-0805 1060,2620 r270 top (schematic designator R78)
R55 "4K7" CC2012-0805 360,2980 r0 top (schematic designator R63)
R56 "330" CC2012-0805 360,3080 r0 top (schematic designator R67)
R57 "4k7" CC2012-0805 3480,3120 r0 top (schematic designator R75)
R58 "680k" CC2012-0805 3760,3080 r0 top (schematic designator R73)
R59 "0" CC2012-0805 3480,3220 r0 top (schematic designator R76)
R60 "4k7" CC2012-0805 4540,3180 r0 top (schematic designator R69)
R61 "0" CC2012-0805 2840,3300 r0 top (schematic designator R2)
R62 "270k" CC2012-0805 4280,3280 r0 top (schematic designator R74)
R63 "4K7" CC2012-0805 380,3440 r0 top (schematic designator R62)
R64 "4k7" CC2012-0805 4540,3520 r0 top (schematic designator R72)
R65 "330" CC2012-0805 380,3540 r0 top (schematic designator R66)
R66 "100" CC2012-0805 2840,3640 r0 top (schematic designator R59)
R67 "4K7" CC2012-0805 380,3900 r0 top (schematic designator R61)
R68 "330" CC2012-0805 380,4000 r0 top (schematic designator R65)
R69 "4k7" CC2012-0805 4540,4160 r0 top (schematic designator R71)
R70 "4K7" CC2012-0805 680,4540 r270 top (schematic designator R11)
R71 "4K7" CC2012-0805 780,4540 r270 top (schematic designator R10)
R72 "4K7" CC2012-0805 880,4540 r270 top (schematic designator R9)
R73 "0" CC2012-0805 2760,4540 r90 top (schematic designator R3)
R74 "0" CC2012-0805 2860,4540 r90 top (schematic designator R6)
R75 "0" CC2012-0805 2960,4540 r90 top (schematic designator R4)
R76 "0" CC2012-0805 3060,4540 r90 top (schematic designator R7)
R77 "560" CC2012-0805 3160,4540 r90 top (schematic designator R64)
R78 "4K7" CC2012-0805 580,4540 r270 top (schematic designator R60)
R79 "0" CC2012-0805 2560,4540 r90 top (schematic designator R8)
R80 "0" CC2012-0805 2460,4540 r270 top (schematic designator R5)
S1 "SPST" PCB_SWITCH 3580,4560 r0 top
SW1 "B3FS" B3FS_SWITCH 260,2800 r0 top (schematic designator SW4)
SW2 "B3FS" B3FS_SWITCH 260,3260 r0 top (schematic designator SW3)
SW3 "B3FS" B3FS_SWITCH 260,3720 r0 top (schematic designator SW2)
SW4 "B3FS" B3FS_SWITCH 260,4180 r0 top (schematic designator SW1)
U1 "SAA7111A" QFP14X14_64 1160,700 r90 top (schematic designator U4)
U2 "SAA7111A" QFP14X14_64 2540,700 r90 top (schematic designator U5)
U3 "SAA7127H" QFP10X10_44 4220,1920 r270 top (schematic designator U6)
U4 "IDT71V124SA15Y" SO-J32 2100,2520 r0 top (schematic designator U2)
U5 "XCF01SVO20C" VO20 820,2660 r90 top (schematic designator U3)
U6 "LP3961ET-3.3" TO220-5V 4500,3000 r270 top (schematic designator U7)
U7 "XC2S300E-6PQ208C" F-QFP28X28-G208/P.5N 2060,3800 r180 top (schematic designator U1)
U8 "TPS3306" SOIC8 4140,3180 r180 top (schematic designator U9)
U9 "LP3961ET-1.8" TO220-5V 4500,3980 r270 top (schematic designator U8)
X1 "24.576MHz" QC49/SMD 760,1080 r90 top
X2 "24.576MHz" QC49/SMD 2140,1080 r90 top

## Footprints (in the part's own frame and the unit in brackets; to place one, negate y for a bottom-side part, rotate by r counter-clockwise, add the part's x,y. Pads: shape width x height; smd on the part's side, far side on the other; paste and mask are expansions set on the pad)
B3FS_SWITCH [mm]
  rect 1.6x1.4 smd: 1(4.01,-2.25) 2(-4,-2.25) 3(4.01,2.24) 4(-4,2.24)
  silkscreen extent -3.16,-3.16 3.15,3.15
CC2012-0805 [mm]
  rect 1.3x1.5 smd: 1(-0.95,0) 2(0.95,0)
  silkscreen extent -1,-0.9 1,0.9
F-QFP28X28-G208/P.5N [mm]
  oval 1.55x0.3 smd: 1(-14.899,12.751)
  rect 1.55x0.3 smd: 2(-14.899,12.251) 3(-14.899,11.751) 4(-14.899,11.251) 5(-14.899,10.751) 6(-14.899,10.251) 7(-14.899,9.751) 8(-14.899,9.251) 9(-14.899,8.751) 10(-14.899,8.251) 11(-14.899,7.751) 12(-14.899,7.251) 13(-14.899,6.751) 14(-14.899,6.251) 15(-14.899,5.751) 16(-14.899,5.251) 17(-14.899,4.751) 18(-14.899,4.251) 19(-14.899,3.751) 20(-14.899,3.251) 21(-14.899,2.751) 22(-14.899,2.251) 23(-14.899,1.751) 24(-14.899,1.251) 25(-14.899,0.751) 26(-14.899,0.251) 27(-14.899,-0.249) 28(-14.899,-0.749) 29(-14.899,-1.249) 30(-14.899,-1.749) 31(-14.899,-2.249) 32(-14.899,-2.749) 33(-14.899,-3.249) 34(-14.899,-3.749) 35(-14.899,-4.249) 36(-14.899,-4.749) 37(-14.899,-5.249) 38(-14.899,-5.749) 39(-14.899,-6.249) 40(-14.899,-6.749) 41(-14.899,-7.249) 42(-14.899,-7.749) 43(-14.899,-8.249) 44(-14.899,-8.749) 45(-14.899,-9.249) 46(-14.899,-9.749) 47(-14.899,-10.249) 48(-14.899,-10.749) 49(-14.899,-11.249) 50(-14.899,-11.749) 51(-14.899,-12.249) 52(-14.899,-12.749) 105(14.901,-12.749) 106(14.901,-12.249) 107(14.901,-11.749) 108(14.901,-11.249) 109(14.901,-10.749) 110(14.901,-10.249) 111(14.901,-9.749) 112(14.901,-9.249) 113(14.901,-8.749) 114(14.901,-8.249) 115(14.901,-7.749) 116(14.901,-7.249) 117(14.901,-6.749) 118(14.901,-6.249) 119(14.901,-5.749) 120(14.901,-5.249) 121(14.901,-4.749) 122(14.901,-4.249) 123(14.901,-3.749) 124(14.901,-3.249) 125(14.901,-2.749) 126(14.901,-2.249) 127(14.901,-1.749) 128(14.901,-1.249) 129(14.901,-0.749) 130(14.901,-0.249) 131(14.901,0.251) 132(14.901,0.751) 133(14.901,1.251) 134(14.901,1.751) 135(14.901,2.251) 136(14.901,2.751) 137(14.901,3.251) 138(14.901,3.751) 139(14.901,4.251) 140(14.901,4.751) 141(14.901,5.251) 142(14.901,5.751) 143(14.901,6.251) 144(14.901,6.751) 145(14.901,7.251) 146(14.901,7.751) 147(14.901,8.251) 148(14.901,8.751) 149(14.901,9.251) 150(14.901,9.751) 151(14.901,10.251) 152(14.901,10.751) 153(14.901,11.251) 154(14.901,11.751) 155(14.901,12.251) 156(14.901,12.751)
  rect 0.3x1.55 smd: 53(-12.749,-14.899) 54(-12.249,-14.899) 55(-11.749,-14.899) 56(-11.249,-14.899) 57(-10.749,-14.899) 58(-10.249,-14.899) 59(-9.749,-14.899) 60(-9.249,-14.899) 61(-8.749,-14.899) 62(-8.249,-14.899) 63(-7.749,-14.899) 64(-7.249,-14.899) 65(-6.749,-14.899) 66(-6.249,-14.899) 67(-5.749,-14.899) 68(-5.249,-14.899) 69(-4.749,-14.899) 70(-4.249,-14.899) 71(-3.749,-14.899) 72(-3.249,-14.899) 73(-2.749,-14.899) 74(-2.249,-14.899) 75(-1.749,-14.899) 76(-1.249,-14.899) 77(-0.749,-14.899) 78(-0.249,-14.899) 79(0.251,-14.899) 80(0.751,-14.899) 81(1.251,-14.899) 82(1.751,-14.899) 83(2.251,-14.899) 84(2.751,-14.899) 85(3.251,-14.899) 86(3.751,-14.899) 87(4.251,-14.899) 88(4.751,-14.899) 89(5.251,-14.899) 90(5.751,-14.899) 91(6.251,-14.899) 92(6.751,-14.899) 93(7.251,-14.899) 94(7.751,-14.899) 95(8.251,-14.899) 96(8.751,-14.899) 97(9.251,-14.899) 98(9.751,-14.899) 99(10.251,-14.899) 100(10.751,-14.899) 101(11.251,-14.899) 102(11.751,-14.899) 103(12.251,-14.899) 104(12.751,-14.899) 157(12.751,14.901) 158(12.251,14.901) 159(11.751,14.901) 160(11.251,14.901) 161(10.751,14.901) 162(10.251,14.901) 163(9.751,14.901) 164(9.251,14.901) 165(8.751,14.901) 166(8.251,14.901) 167(7.751,14.901) 168(7.251,14.901) 169(6.751,14.901) 170(6.251,14.901) 171(5.751,14.901) 172(5.251,14.901) 173(4.751,14.901) 174(4.251,14.901) 175(3.751,14.901) 176(3.251,14.901) 177(2.751,14.901) 178(2.251,14.901) 179(1.751,14.901) 180(1.251,14.901) 181(0.751,14.901) 182(0.251,14.901) 183(-0.249,14.901) 184(-0.749,14.901) 185(-1.249,14.901) 186(-1.749,14.901) 187(-2.249,14.901) 188(-2.749,14.901) 189(-3.249,14.901) 190(-3.749,14.901) 191(-4.249,14.901) 192(-4.749,14.901) 193(-5.249,14.901) 194(-5.749,14.901) 195(-6.249,14.901) 196(-6.749,14.901) 197(-7.249,14.901) 198(-7.749,14.901) 199(-8.249,14.901) 200(-8.749,14.901) 201(-9.249,14.901) 202(-9.749,14.901) 203(-10.249,14.901) 204(-10.749,14.901) 205(-11.249,14.901) 206(-11.749,14.901) 207(-12.249,14.901) 208(-12.749,14.901)
  round 1 smd: FID1(-14.899,-14.899) FID2(14.901,14.901)
  Top Layer keep-out circle w0.2: c-14.899,-14.899 r1.4
  Top Layer keep-out circle w0.2: c14.901,14.901 r1.4
  silkscreen extent -15.02,-13.72 13.73,13.73
HDR1X2 [mm]
  rect 1.5x1.5 hole 0.9: 1(0,0)
  round 1.5 hole 0.9: 2(2.54,0)
  silkscreen extent -1.27,-1.27 3.81,1.27
HDR2X4 [mm]
  rect 1.5x1.5 hole 0.9: 1(0,0)
  round 1.5 hole 0.9: 2(0,2.54) 3(2.54,0) 4(2.54,2.54) 5(5.08,0) 6(5.08,2.54) 7(7.62,0) 8(7.62,2.54)
  silkscreen extent -1.27,-1.27 8.89,3.81
HDR2X5 [mm]
  rect 1.5x1.5 hole 0.9: 1(0,0)
  round 1.5 hole 0.9: 2(0,2.54) 3(2.54,0) 4(2.54,2.54) 5(5.08,0) 6(5.08,2.54) 7(7.62,0) 8(7.62,2.54) 9(10.16,0) 10(10.16,2.54)
  silkscreen extent -1.27,-1.27 11.43,3.81
HDR2X10 [mm]
  rect 1.5x1.5 hole 0.9: 1(0,0)
  round 1.5 hole 0.9: 2(0,2.54) 3(2.54,0) 4(2.54,2.54) 5(5.08,0) 6(5.08,2.54) 7(7.62,0) 8(7.62,2.54) 9(10.16,0) 10(10.16,2.54) 11(12.7,0) 12(12.7,2.54) 13(15.24,0) 14(15.24,2.54) 15(17.78,0) 16(17.78,2.54) 17(20.32,0) 18(20.32,2.54) 19(22.86,0) 20(22.86,2.54)
  silkscreen extent -1.27,-1.27 24.13,3.81
MCCT-B [mm]
  rect 2x2.2 smd: 1(-1.5,0) 2(1.5,0)
  silkscreen extent -2.3,-1.6 1.8,1.6
MCCTD [mm]
  rect 2.6x4.3 smd: 1(0,0) 2(6,0)
  silkscreen extent -2.8,-2.5 7.65,2.5
PCB_SWITCH [mm]
  round 2 hole 1.1: 1(0,-5.08) 2(0,-2.54) 3(0,0)
  silkscreen extent -2.54,-6.63 2.54,1.5
PWR2.5 [mm]
  round 4 hole 3: 1(13.7,0) 2(10.6,-5) 3(7.5,0)
  silkscreen extent 0,-4.47 14.3,4.5
QC49/SMD [mm]
  rect 5x2 smd: 1(-4.75,0) 2(4.75,0)
  silkscreen extent -6.75,-2.4 5.7,2.4
QFP10X10_44 [mm]
  oval 1.8x0.5 smd: 1(0,0)
  rect 1.8x0.5 smd: 2(0,-0.8) 3(0,-1.6) 4(0,-2.4) 5(0,-3.2) 6(0,-4) 7(0,-4.8) 8(0,-5.6) 9(0,-6.4) 10(0,-7.2) 11(0,-8) 23(12,-8) 24(12,-7.2) 25(12,-6.4) 26(12,-5.6) 27(12,-4.8) 28(12,-4) 29(12,-3.2) 30(12,-2.4) 31(12,-1.6) 32(12,-0.8) 33(12,0)
  rect 0.5x1.8 smd: 12(2,-10) 13(2.8,-10) 14(3.6,-10) 15(4.4,-10) 16(5.2,-10) 17(6,-10) 18(6.8,-10) 19(7.6,-10) 20(8.4,-10) 21(9.2,-10) 22(10,-10) 34(10,2) 35(9.2,2) 36(8.4,2) 37(7.6,2) 38(6.8,2) 39(6,2) 40(5.2,2) 41(4.4,2) 42(3.6,2) 43(2.8,2) 44(2,2)
  silkscreen extent -2.4,-12.4 14.3,4.3
QFP14X14_64 [mm]
  oval 1.8x0.5 smd: 1(0,0)
  rect 1.8x0.5 smd: 2(0,-0.8) 3(0,-1.6) 4(0,-2.4) 5(0,-3.2) 6(0,-4) 7(0,-4.8) 8(0,-5.6) 9(0,-6.4) 10(0,-7.2) 11(0,-8) 12(0,-8.8) 13(0,-9.6) 14(0,-10.4) 15(0,-11.2) 16(0,-12) 33(16,-12) 34(16,-11.2) 35(16,-10.4) 36(16,-9.6) 37(16,-8.8) 38(16,-8) 39(16,-7.2) 40(16,-6.4) 41(16,-5.6) 42(16,-4.8) 43(16,-4) 44(16,-3.2) 45(16,-2.4) 46(16,-1.6) 47(16,-0.8) 48(16,0)
  rect 0.5x1.8 smd: 17(2,-14) 18(2.8,-14) 19(3.6,-14) 20(4.4,-14) 21(5.2,-14) 22(6,-14) 23(6.8,-14) 24(7.6,-14) 25(8.4,-14) 26(9.2,-14) 27(10,-14) 28(10.8,-14) 29(11.6,-14) 30(12.4,-14) 31(13.2,-14) 32(14,-14) 49(14,2) 50(13.2,2) 51(12.4,2) 52(11.6,2) 53(10.8,2) 54(10,2) 55(9.2,2) 56(8.4,2) 57(7.6,2) 58(6.8,2) 59(6,2) 60(5.2,2) 61(4.4,2) 62(3.6,2) 63(2.8,2) 64(2,2)
  silkscreen extent -2.4,-16.4 18.3,4.3
RB8/3.5 [mil]
  rect 70x70 hole 27.56: 1(0,60)
  round 70 hole 27.56: 2(0,-60)
  silkscreen extent -160,-160 160,160
RCA_MR551L [mm] "Schurter RCA PCB Socket (Farnell 152-396)"
  round 3.5 hole 2.5: 1(8,5.3) 2(0,0)
  round 1.3 hole 1.5 unplated: M1(0,3.75) M2(0,-3.75)
  round 1.5 hole 1.7 unplated: M3(6.5,0)
  silkscreen extent -2,-5.5 10.5,5.5
"SCREW M3" [mil]
  round 270 hole 125: 1(0,0)
SIMID1008-A [mm]
  rect 1.05x1.6 smd: 1(-1.25,0) 2(1.25,0)
  silkscreen extent -1,-1.2 1,1.2
"SMD _LED" [mm]
  rect 1.3x1.6 smd: 1(0.95,0) 2(-0.95,0)
  silkscreen extent -2.13,-1.15 2,1.15
SO-J32 [mm]
  rect 0.6x2.2 smd: 1(-9.525,-3.6) 2(-8.255,-3.6) 3(-6.985,-3.6) 4(-5.715,-3.6) 5(-4.445,-3.6) 6(-3.175,-3.6) 7(-1.905,-3.6) 8(-0.635,-3.6) 9(0.635,-3.6) 10(1.905,-3.6) 11(3.175,-3.6) 12(4.445,-3.6) 13(5.715,-3.6) 14(6.985,-3.6) 15(8.255,-3.6) 16(9.525,-3.6) 17(9.525,3.6) 18(8.255,3.6) 19(6.985,3.6) 20(5.715,3.6) 21(4.445,3.6) 22(3.175,3.6) 23(1.905,3.6) 24(0.635,3.6) 25(-0.635,3.6) 26(-1.905,3.6) 27(-3.175,3.6) 28(-4.445,3.6) 29(-5.715,3.6) 30(-6.985,3.6) 31(-8.255,3.6) 32(-9.525,3.6)
  silkscreen extent -10.5,-4.19 10.33,4.19
SOIC8 [mm]
  rect 1.5x0.5 smd: 1(0,0) 2(0,-1.27) 3(0,-2.54) 4(0,-3.81) 5(6,-3.81) 6(6,-2.54) 7(6,-1.27) 8(6,0)
  silkscreen extent 1.1,-4.5 4.9,0.7
TO220-5V [mil] "TO220 5-lead, molded, stagger bend package."
  round 80 hole 50: 1(0,-157.48) 2(66.93,0) 3(133.86,-157.48) 4(200.79,0) 5(267.72,-157.48)
  silkscreen extent -67,-20 335,169
VO20 [mm]
  rect 0.3x1.65 smd: 1(-2.925,-2.775) 2(-2.275,-2.775) 3(-1.625,-2.775) 4(-0.975,-2.775) 5(-0.325,-2.775) 6(0.325,-2.775) 7(0.975,-2.775) 8(1.625,-2.775) 9(2.275,-2.775) 10(2.925,-2.775) 11(2.925,2.775) 12(2.275,2.775) 13(1.625,2.775) 14(0.975,2.775) 15(0.325,2.775) 16(-0.325,2.775) 17(-0.975,2.775) 18(-1.625,2.775) 19(-2.275,2.775) 20(-2.925,2.775)
  silkscreen extent -3.75,-2.9 3.3,1.55

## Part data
C1 C3 C4 C5 C6 C7 C8 C9 C10 C11 C12 C13 C14 C15 C16 C17 C19 C20 C21 C22 C23 C24 C25 C26 C27 C28 C29 C30 C31 C32 C33 C34 C35 C36 C38 C39 C40 C42 C43 C44 C46 C47 C48 C49 C50 C51 C52 C53 C54 C55 C56 C57 C59 C60 C61 C62 C63 C64 C65 C66 C67 C68 C69 C70 C73 C74 C75 C76 C77 C78 C79 C81 C82 C83 C84 C85 C86 C88 C89 C90 C91 C93 C94 C95 C97 C98 C99 C100 C101 C102 C103 C104 C105 C106 C107 C108 C109 C110 C111 C112 C113 C114: library part CAP, "Capacitor"
C2 C18 C37 C41 C45 C58 C71 C72 C80 C87 C92 C96: library part CAP_POLAR, "Polar Capacitor"
HDR1 HDR2 HDR3 HDR4: "Header, 2-Pin"
J1 J2 J3 J4 J5: "RCA Socket"
J6: "Low Voltage Power Supply Sonnector"
JP1: library part "Header 2X2", "Header, 2-Pin, Dual row"
JP2 JP3: "Header, 10-Pin, Dual row"
JP4: "Header, 5-Pin, Dual row"
L1 L2 L6 L8 L9 L10 L11 L12 L13 L14: library part FERRITE_BEAD, "BMB Series Ferrite Chip Bead"
LED1 LED2 LED3 LED4 LED5: "Typical RED GaAs SMD LED Agilent make"
R1 R2 R3 R4 R5 R6 R7 R8 R9 R10 R11 R12 R13 R14 R15 R16 R17 R18 R19 R20 R21 R22 R23 R24 R25 R26 R27 R28 R29 R30 R31 R32 R33 R34 R35 R36 R37 R38 R39 R40 R41 R42 R43 R44 R45 R46 R47 R48 R49 R50 R51 R52 R53 R54 R55 R56 R57 R58 R59 R60 R61 R62 R63 R64 R65 R66 R67 R68 R69 R70 R71 R72 R73 R74 R75 R76 R77 R78 R79 R80: library part RES, "Resistor"
S1: library part PCB_MOUNT_SWITCH, "SPDT Subminiature Toggle Switch"
SW1 SW2 SW3 SW4: "SPNA SMD Keyboard Switch"
U1 U2: "Philips Enhanced Video Input Processor"
U3: library part SAA7121H, "Philips Digital Video Encoder"
U4: "128K x 8 bit Fast Static RAM"
U5: "XCF00S Series, Platform Flash In-System Programmable Configuration 3.3V PROM, 1-Megabit, Commercial Grade"
U6 U9: library part LP3961ET, "800mA Fast UL Dropout Regulator"
U7: "Spartan-IIE 1.8V FPGA, 208-Pin PQFP, Standard Performance, Commercial Grade"
U8: "TI Dual Voltage MPU Supervisory Circuit"
X1 X2: library part CRYSTAL

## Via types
v1: diameter 40, hole 28, Top Layer to Bottom Layer, 433 vias

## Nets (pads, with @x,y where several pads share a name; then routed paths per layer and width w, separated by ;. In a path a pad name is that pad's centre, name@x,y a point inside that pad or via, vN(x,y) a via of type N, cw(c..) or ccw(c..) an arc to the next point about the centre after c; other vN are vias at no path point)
A0: U4.1 U7.162 | length 1001.4
  Top Layer w8: U7.162@1656.43,3213.36 1656.43,3169.06 1490,3002.63 1490,2800 1725,2565 U4.1@1725,2378.27
A1: U4.2 U7.164 | length 1090.8
  Top Layer w8: U7.164@1695.8,3213.36 1695.8,3163.18 1522,2989.37 1522,2813.25 1598.25,2737 1733,2737 1750,2720 1750,2530 1775,2505 U4.2@1775,2378.27
A2: U4.3 U7.166 | length 1105.3
  Top Layer w8: U7.166@1735.17,3213.36 1735.17,3157.29 1554,2976.12 1554,2826.51 1611.51,2769 1753,2769 1800,2722 1800,2530 1825,2505 U4.3@1825,2378.27
A3: U4.4 U7.168 | length 1119.7
  Top Layer w8: U7.168@1774.54,3213.36 1774.54,3151.41 1586,2962.86 1586,2839.76 1624.76,2801 1773,2801 1850,2724 1850,2530 1875,2505 U4.4@1875,2378.27
A4: U4.13 U7.194 | length 871.8
  Top Layer w8: U7.194@2286.35,3213.36 2286.35,3156.27 2325,3117.63 2325,2762.63 2350,2737.63 2350,2530 2325,2505 U4.13@2325,2378.27
A5: U4.14 U7.199 | length 1046.7
  Top Layer w8: U4.14@2375,2378.27 2375,2505 2400,2530 2400,2722 2440,2762 2538.12,2762 2566,2789.88 2566,2983.49 2384.78,3164.71 U7.199@2384.78,3213.36
A6: U4.15 U7.201 | length 1026.4
  Top Layer w8: U7.201@2424.15,3213.36 2424.15,3170.6 2598,2996.75 2598,2776.63 2551.37,2730 2470,2730 2450,2710 2450,2530 2425,2505 U4.15@2425,2378.27
A7: U4.16 U7.203 | length 968.3
  Top Layer w8: U7.203@2463.52,3213.36 2463.52,3176.48 2630,3010 2630,2710 2475,2555 U4.16@2475,2378.27
A8: U4.17 U7.202 | length 697.7
  Top Layer w8: U7.202@2443.83,3213.36 2443.83,3173.54 2614,3003.37 2614,2770 2505.73,2661.73 U4.17@2475,2661.73
A9: U4.18 U7.200 | length 745.7
  Top Layer w8: U7.200@2404.46,3213.36 2404.46,3167.65 2582,2990.12 2582,2783.25 2544.75,2746 2450,2746 2425,2721 U4.18@2425,2661.73
A10: U4.19 U7.198 | length 761.3
  Top Layer w8: U7.198@2365.09,3213.36 2365.09,3161.77 2550,2976.86 2550,2796.51 2531.49,2778 2428,2778 2375,2725 U4.19@2375,2661.73
A11: U4.20 U7.193 | length 575.8
  Top Layer w8: U7.193@2266.67,3213.36 2266.67,3153.33 2309,3111 2309,2753.63 2325,2737.63 U4.20@2325,2661.73
A12: U4.21 U7.191 | length 571.4
  Top Layer w8: U7.191@2227.3,3213.36 2227.3,3147.45 2275,3099.75 U4.21@2275,2661.73
A13: U4.29 U7.169 | length 833.1
  Top Layer w8: U7.169@1794.23,3213.36 1794.23,3148.47 1602,2956.24 1602,2846.39 1631.39,2817 1783,2817 1875,2725 U4.29@1875,2661.73
A14: U4.30 U7.167 | length 818.7
  Top Layer w8: U7.167@1754.86,3213.36 1754.86,3154.35 1570,2969.49 1570,2833.14 1618.14,2785 1763,2785 1825,2723 U4.30@1825,2661.73
A15: U4.31 U7.165 | length 804.2
  Top Layer w8: U7.165@1715.49,3213.36 1715.49,3160.23 1538,2982.75 1538,2819.88 1604.88,2753 1743,2753 1775,2721 U4.31@1775,2661.73
A16: U4.32 U7.163 | length 756.2
  Top Layer w8: U7.163@1676.12,3213.36 1676.12,3166.12 1506,2996 1506,2806.63 1650.9,2661.73 U4.32@1725,2661.73
AIN0: J5.1 R8.1 R17.1 | length 5460.7
  Top Layer w8: v1(1780,200) R8.1@1780,262.6 ; v1(3160,200) R17.1@3160,262.6
  Bottom Layer w8: J5.1@474.96,2468.66 260,2253.7 260,550 440,370 440,170 510,100 1630,100 1730,200 v1(1780,200) 1830,200 1930,100 3060,100 v1(3160,200)
AIN1: J4.1 R6.1 R15.1 | length 4612.4
  Top Layer w8: v1(1580,200) R6.1@1580,262.6 ; v1(2960,200) R15.1@2960,262.6
  Bottom Layer w8: J4.1@474.96,1928.66 300,1753.7 300,570 480,390 480,230 580,130 1510,130 v1(1580,200) 1620,240 2270,240 2380,130 2890,130 v1(2960,200)
AIN2: J3.1 R4.1 R13.1 | length 3764.1
  Top Layer w8: v1(1380,200) R4.1@1380,262.6 ; v1(2760,200) R13.1@2760,262.6
  Bottom Layer w8: J3.1@474.96,1388.66 340,1253.7 340,590 520,410 520,290 650,160 1340,160 v1(1380,200) 1460,280 2330,280 2450,160 2720,160 v1(2760,200)
AIN3: J1.1 R2.1 R11.1 | length 2674.2
  Top Layer w8: v1(1180,200) R2.1@1180,262.6 ; v1(2560,200) R11.1@2560,262.6
  Bottom Layer w8: J1.1@474.96,848.66 474.96,685.04 780,380 840,320 1010,320 1130,200 v1(1180,200) 1230,200 1350,320 2440,320 v1(2560,200)
BLUE: JP1.5 R27.2 | length 1193.6
  Top Layer w8: R27.2@4237.4,1100 4240,1102.6 v1(4240,1180)
  Bottom Layer w8: JP1.5@3920,200 3970,250 3970,340 4140,510 4140,820 4240,920 v1(4240,1180)
CCLK: U5.3 U7.155 | length 1644.5
  Top Layer w8: v1(700,3240) 660,3200 660,3040 796,2904 796,2646.63 846.6,2596.02 U5.3@929.25,2596.02 ; v1(1200,3340) 1400,3340 1422.31,3317.69 U7.155@1473.36,3317.69
  Bottom Layer w8: v1(700,3240) 800,3340 v1(1200,3340)
CLKOUT: JP3.10 R49.1 U3.4 U7.40 U7.81 | length 5615.4
  Top Layer w8: v1(1950,4500) 2010.76,4439.24 U7.81@2010.76,4386.59 ; v1(2490,4090) 2514.28,4065.72 U7.40@2646.59,4065.72 2735.72,4065.72 2860,4190 3050,4190 3180,4060 3180,2640 2760,2220 JP3.10@2760,2170 2810,2120 2810,2040 2860,1990 3790,1990 3920,2120 4122.6,2120 R49.1@4182.6,2060 4125.51,2002.91 U3.4@4125.51,1920
  Bottom Layer w8: v1(1950,4500) 1950,4440 2000,4390 2320,4390 2490,4220 v1(2490,4090)
CSBAR: U4.5 U7.173 | length 856.6
  Top Layer w8: U7.173@1872.97,3213.36 1872.97,2757.03 1900,2730 1900,2530 1925,2505 U4.5@1925,2378.27
D0: U4.6 U7.178 | length 901
  Top Layer w8: U7.178@1970,3220 1970,3213.36 1970,3170 1926,3126 1926,2796.63 2000,2722.63 2000,2530 1975,2505 U4.6@1975,2378.27
D1: U4.7 U7.180 | length 905.4
  Top Layer w8: U7.180@2010.76,3213.36 2010.76,3165.51 1958,3112.75 1958,2809.88 2050,2717.88 2050,2600 2025,2575 U4.7@2025,2378.27
D2: U4.10 U7.187 | length 889.1
  Top Layer w8: U7.187@2148.56,3213.36 2148.56,3158.3 2227,3079.86 2227,2764 2200,2737 2200,2470 2175,2445 U4.10@2175,2378.27
D3: U4.11 U7.189 | length 878.6
  Top Layer w8: U7.189@2187.93,3213.36 2187.93,3164.19 2259,3093.12 2259,2749 2250,2740 2250,2530 2225,2505 U4.11@2225,2378.27
D4: U4.22 U7.188 | length 590.1
  Top Layer w8: U7.188@2168.24,3213.36 2168.24,3161.25 2243,3086.49 2243,2755.63 2225,2737.63 U4.22@2225,2661.73
D5: U4.23 U7.181 | length 862.4
  Top Layer w8: U7.181@2030.45,3213.36 2030.45,3162.57 1974,3106.12 1974,2816.51 2050.51,2740 2080,2740 2100,2720 2100,2600 2120,2580 2160,2580 2175,2595 U4.23@2175,2661.73
D6: U4.26 U7.179 | length 606.3
  Top Layer w8: U7.179@1991.08,3213.36 1991.08,3168.45 1942,3119.37 1942,2803.25 2025,2720.25 U4.26@2025,2661.73
D7: U4.27 U7.176 | length 587.7
  Top Layer w8: U7.176@1932.02,3213.36 1932.02,3170 1910,3147.98 1910,2790 1975,2725 U4.27@1975,2661.73
DIN: U5.1 U7.153 | length 1779.2
  Top Layer w8: v1(700,3340) 640,3280 640,3030 780,2890 780,2640 875.16,2544.84 U5.1@929.25,2544.84 ; v1(1280,3390) 1312.94,3357.06 U7.153@1473.36,3357.06
  Bottom Layer w8: v1(700,3340) 750,3390 v1(1280,3390)
DONE: R71.2 U5.10 U7.104 | length 2725.2
  Top Layer w8: R71.2@780,4502.6 v1(780,4450) 780,4340 800,4320 800,3060 1010,2850 1010,2800 985.16,2775.16 U5.10@929.25,2775.16 ; v1@1491.16,4410 1514.57,4386.59 U7.104@1558.01,4386.59
  Bottom Layer w8: v1(780,4450) 820,4490 970,4490 1050,4410 v1(1490,4410)
GND: C1.2 C2.2 C4.1 C7.1 C9.2 C10.2 C11.2 C13.1 C16.1 C18.2 C19.1 C20.1 C21.1 C22.1 C23.1 C24.1 C25.1 C26.1 C27.2 C28.2 C29.2 C30.2 C31.2 C32.2 C33.2 C35.2 C36.2 C37.2 C38.2 C39.2 C40.2 C41.2 C42.2 C43.2 C44.2 C45.2 C46.2 C47.2 C48.2 C49.2 C50.2 C51.2 C52.2 C53.2 C54.2 C55.1 C56.2 C57.2 C58.2 C59.1 C60.1 C61.2 C62.2 C63.2 C64.2 C65.1 C66.2 C67.2 C68.2 C69.2 C70.2 C71.2 C72.2 C73.2 C74.2 C75.2 C76.2 C77.2 C78.2 C79.2 C80.2 C81.1 C82.2 C83.2 C84.2 C85.2 C86.2 C87.2 C88.2 C89.2 C90.2 C91.2 C92.2 C93.2 C94.2 C95.2 C96.2 C97.1 C98.2 C99.1 C100.2 C101.2 C102.2 C103.2 C104.2 C105.2 C106.2 C107.2 C108.2 C109.2 C110.1 C111.2 C112.1 C113.2 C114.2 HDR1.1 HDR1.2 HDR2.1 HDR2.2 HDR3.1 HDR3.2 HDR4.1 HDR4.2 J1.2 J2.2 J3.2 J4.2 J5.2 J6.2 J6.3 JP1.2 JP1.4 JP1.6 JP1.8 JP2.20 JP3.20 JP4.9 JP4.10 M1.1 M2.1 M3.1 M4.1 R1.1 R3.1 R5.1 R7.1 R9.1 R12.1 R14.1 R16.1 R29.1 R34.1 R62.2 R74.2 R76.2 R77.2 R79.2 SW1.1 SW1.2 SW2.1 SW2.2 SW3.1 SW3.2 SW4.1 SW4.2 U1.5 U1.9 U1.13 U1.16 U1.19 U1.26 U1.32 U1.40 U1.56 U1.61 U2.5 U2.9 U2.13 U2.16 U2.19 U2.26 U2.32 U2.40 U2.56 U3.2 U3.3 U3.5 U3.18 U3.19 U3.21 U3.22 U3.32 U3.33 U3.35 U3.38 U3.44 U4.9 U4.25 U5.11 U6.3 U7.1 U7.12 U7.19 U7.25 U7.32 U7.39 U7.51 U7.65 U7.72 U7.79 U7.85 U7.92 U7.103 U7.117 U7.124 U7.131 U7.137 U7.144 U7.158 U7.170 U7.177 U7.183 U7.190 U7.197 U8.4 U9.3 | length 591.2
  Top Layer w8: SW1.2@102.52,2711.42 103.94,2710 v1(170,2710) ; SW2.2@102.52,3171.42 103.94,3170 v1(170,3170) ; SW3.2@102.52,3631.42 168.58,3631.42 v1(170,3630) ; SW4.2@102.52,4091.42 103.94,4090 v1(180,4090) ; v1(350,2710) 416.46,2710 SW1.1@417.87,2711.42 ; v1(350,3170) 416.46,3170 SW2.1@417.87,3171.42 ; v1(350,3630) 416.46,3630 SW3.1@417.87,3631.42 ; v1(350,4090) 351.42,4091.42 SW4.1@417.87,4091.42 ; HDR3.1@540,2800 HDR3.1@564.84,2775.16
  other v1: 500,160 700,200 780,200 860,200 1080,200 1280,200 1480,200 1680,200 2360,200 2460,200 2660,200 2860,200 3060,200 3260,200 550,210 630,260 3520,340 1130,390 1280,400 2660,400 2960,400 1580,410 600,460 3450,460 2100,560 2000,580 3380,580 650,610 990,610 2370,620 1700,700 2000,700 3080,700 3380,700 1320,800 1410,800 1520,800 2860,800 2300,810 920,820 2000,820 3380,820 2750,840 1600,900 160,910 3800,930 3980,930 4160,930 2780,960 3680,1000 1600,1060 2980,1060 760,1080 2140,1080 3380,1080 1200,1100 2580,1100 1930,1130 2280,1150 880,1170 4040,1180 4120,1180 4320,1180 4580,1180 1600,1200 2580,1220 3820,1220 1200,1230 1490,1230 2880,1240 3540,1270 3380,1340 3820,1340 1940,1410 3350,1420 3820,1440 4580,1440 160,1450 4300,1460 1870,1470 2590,1490 2030,1520 2270,1520 1800,1540 4000,1540 4220,1540 4580,1540 2590,1560 3520,1560 720,1580 820,1580 940,1580 3920,1600 1300,1620 1700,1620 3160,1620 4220,1650 3520,1660 4580,1660 3240,1700 3140,1740 4180,1820 4300,1920 160,1990 3920,2060 4580,2060 2020,2120 2120,2120 2220,2120 680,2160 3740,2180 4120,2180 1360,2250 3500,2250 2970,2260 4580,2280 780,2300 3440,2320 4510,2350 840,2360 2110,2470 3640,2520 2070,2530 2150,2530 2600,2540 1580,2580 2700,2660 3900,2700 4020,2700 1060,2720 2860,2730 3660,2780 700,2820 940,2820 2380,2820 2480,2820 2700,2820 1830,2840 1650,2870 2020,2880 1650,2930 2020,2940 2100,2940 3860,2980 3000,3020 3660,3180 2990,3200 2720,3240 1180,3260 4380,3280 1760,3300 2380,3310 1560,3360 4140,3380 2160,3420 1760,3440 1940,3440 2940,3440 1560,3460 1180,3480 2290,3480 3000,3490 3810,3500 2000,3540 2940,3540 2440,3560 1180,3580 3810,3580 2560,3650 1180,3680 2940,3740 1180,3780 1760,3780 3000,3790 2160,3800 2940,3840 2420,3860 2550,3920 1760,3960 3480,3960 1160,3980 3010,4040 1160,4080 3080,4090 3010,4140 3480,4140 2270,4190 1880,4200 4360,4230 1980,4240 2220,4260 2560,4280 1240,4300 1740,4310 1920,4310 1180,4360 1430,4470 1780,4630 1880,4630 2060,4630 2160,4630 2260,4630 2360,4630 2560,4630 2660,4630 2860,4630 3060,4630
INIT: R72.2 U5.8 U7.107 | length 2670.5
  Top Layer w8: R72.2@880,4502.6 v1(880,4450) 880,4380 820,4320 820,3070 1030,2860 1030,2770 983.98,2723.98 U5.8@929.25,2723.98 ; v1(1380,4220) 1422.57,4262.57 U7.107@1473.36,4262.57
  Bottom Layer w8: v1(880,4450) 980,4450 1170,4260 1340,4260 v1(1380,4220)
KEY0: R78.2 SW4.3 SW4.4 U7.75 | length 2549.1
  Top Layer w8: SW4.4@102.52,4268.19 SW4.3@417.87,4268.19 480,4330.32 480,4460 522.6,4502.6 R78.2@580,4502.6 v1(580,4450) ; v1(2070,4200) 2128.87,4258.87 U7.75@2128.87,4386.59
  Bottom Layer w8: v1(580,4450) 620,4450 890,4180 1630,4180 1660,4150 1960,4150 2010,4200 v1(2070,4200)
KEY1: R67.2 SW3.3 SW3.4 U7.74 | length 2516.1
  Top Layer w8: SW3.4@102.52,3808.19 SW3.3@417.87,3808.19 417.4,3808.66 R67.2@417.4,3900 460,3900 500,3940 500,4020 620,4140 v1(700,4140) ; v1(2060,4120) 2148.56,4208.56 U7.74@2148.56,4386.59
  Bottom Layer w8: v1(700,4140) 1610,4140 1640,4110 1980,4110 1990,4120 v1(2060,4120)
KEY2: R63.2 SW2.3 SW2.4 U7.73 | length 3050.6
  Top Layer w8: SW2.4@102.52,3348.19 SW2.3@417.87,3348.19 417.4,3348.66 R63.2@417.4,3440 460,3440 500,3480 500,3880 640,4020 v1(700,4020) ; v1(2140,4040) 2168.24,4068.24 U7.73@2168.24,4386.59
  Bottom Layer w8: v1(700,4020) 940,4020 1036,3924 1474,3924 1590,4040 v1(2140,4040)
KEY3: R55.2 SW1.3 SW1.4 U7.71 | length 3489.8
  Top Layer w8: SW1.4@102.52,2888.19 SW1.3@417.87,2888.19 397.4,2908.66 R55.2@397.4,2980 440,2980 540,3080 540,3810 620,3890 v1(700,3890) ; v1(2060,3960) 2140,3960 2220,4040 2220,4210 2260,4250 2260,4280 2207.61,4332.39 U7.71@2207.61,4386.59
  Bottom Layer w8: v1(700,3890) 1500,3890 1510,3900 2000,3900 v1(2060,3960)
LED0: R68.2 U7.63 | length 2390.7
  Top Layer w8: R68.2@417.4,4000 460,4000 480.16,4020.16 480.16,4040 600.16,4160 620,4160 v1(700,4240) ; v1(2340,4200) 2380,4200 2400,4220 2400,4270 2365.09,4304.91 U7.63@2365.09,4386.59
  Bottom Layer w8: v1(700,4240) 807.37,4240 870.16,4177.21 887.37,4160 1620,4160 1650,4130 1970,4130 2000,4160 2180,4160 2260,4240 2300,4240 v1(2340,4200)
LED1: R65.2 U7.62 | length 2849.3
  Top Layer w8: R65.2@417.4,3540 460,3540 480,3560 480,3897.37 520,3937.37 520,4017.37 582.63,4080 v1(620,4080) ; v1(2280,4120) 2360,4120 2420,4180 2420,4280 2384.78,4315.22 U7.62@2384.78,4386.59
  Bottom Layer w8: v1(620,4080) 917.37,4080 996.72,4000.65 1057.37,3940 1460,3940 1580,4060 2070,4060 2130,4120 v1(2280,4120)
LED2: R56.2 U7.61 | length 3193.7
  Top Layer w8: R56.2@397.4,3080 460,3080 520,3140 520,3850 v1(620,3950) ; v1(2340,4040) 2404.46,4104.46 2404.46,4130 2440,4165.54 2440,4290 2404.46,4325.54 U7.61@2404.46,4386.59
  Bottom Layer w8: v1(620,3950) 980,3950 1022,3908 1258,3908 1490,3908 1502,3920 1930,3920 2010,4000 2170,4000 2210,4040 v1(2340,4040)
LED3: R53.2 U7.60 | length 3586.3
  Top Layer w8: R53.2@397.4,2620 450,2620 480,2650 480,2997.37 560,3077.37 560,3760 v1(620,3820) ; v1(2280,3960) 2330,3960 2424.15,4054.15 2424.15,4120 2460,4155.85 2460,4300 2424.15,4335.85 U7.60@2424.15,4386.59
  Bottom Layer w8: v1(620,3820) 690,3820 740,3870 1510,3870 1520,3880 2050,3880 2130,3960 v1(2280,3960)
LLCA: JP2.10 R21.1 U7.80 U7.112 U7.182 | length 5059.8
  Top Layer w8: JP2.10@1360,2170 1410,2120 1410,2020 1990,1440 1990,992.6 R21.1@1937.4,940 ; U7.112@1473.36,4164.15 1565.85,4164.15 1620,4110 1910,4110 ; v1(2000,3380) 2050.13,3329.87 U7.182@2050.13,3213.36 ; U7.80@2030.45,4386.59 2030.45,4340.45 1940,4250 1940,4140 1910,4110 ; v1(2090,3470) 2090,3520 1940,3670 1940,4080 1910,4110
  Bottom Layer w8: JP2.10@1360,2170 1290,2240 1290,3010 1660,3380 v1(2000,3380) v1(2090,3470)
LLCB: JP2.19 R22.1 U7.125 U7.185 | length 5514
  Top Layer w8: v1(1440,3060) 1440,2572.63 1810,2202.63 1810,2160 1860,2110 JP2.19@1860,2070 1860,2010 2060,1810 3250,1810 3440,1620 3440,1062.6 R22.1@3317.4,940 ; U7.125@1473.36,3908.24 1621.76,3908.24 1667.35,3862.65 1667.35,3792.65 v1(2080,3380) 2109.19,3350.81 U7.185@2109.19,3213.36
  Bottom Layer w8: v1(1440,3060) 1520,3140 1840,3140 v1(2080,3380)
M0: R73.2 R74.1 U7.52 | length 452.5
  Top Layer w8: U7.52@2646.59,4301.94 2701.94,4301.94 2860,4460 R74.1@2860,4502.6 2842.6,4520 2820,4520 2762.6,4577.4 R73.2@2760,4577.4
M1: R75.2 R76.1 U7.50 | length 615.2
  Top Layer w8: U7.50@2646.59,4262.57 2692.57,4262.57 2820,4390 2910,4480 2910,4527.4 R75.2@2960,4577.4 2977.4,4560 2980,4560 3020,4520 3042.6,4520 R76.1@3060,4502.6 R76.1@3047.4,4502.6
M2: R79.1 R80.2 U7.54 | length 223.4
  Top Layer w8: R80.2@2460,4502.6 R79.1@2560,4502.6 2542.26,4484.86 U7.54@2542.26,4386.59
MPA0: JP2.2 R30.1 U7.111 | length 4796.2
  Top Layer w8: R30.1@1200,1557.4 1120,1637.4 1120,1880 1010,1990 1010,2120 JP2.2@960,2170 960,2220 1120,2380 1120,2800 840,3080 840,4300 1130,4590 v1(1620,4590) ; U7.111@1473.36,4183.83 1580.91,4183.83 1634.75,4130 1780,4130 1800,4150 v1(1800,4190)
  Bottom Layer w8: v1(1620,4590) 1800,4410 v1(1800,4190)
MPA1: JP2.3 R40.1 U7.110 | length 4397.9
  Top Layer w8: R40.1@1200,1737.4 1200,1860 1060,2000 JP2.3@1060,2070 1060,2110 1010,2160 1010,2230 1140,2360 1140,2810 860,3090 860,4290 1140,4570 1580,4570 v1(1660,4490) ; U7.110@1473.36,4203.52 1583.85,4203.52 1641.37,4146 1706,4146 1740,4180 v1(1740,4240)
  Bottom Layer w8: v1(1660,4490) 1660,4320 v1(1740,4240)
MPA2: JP2.4 R31.1 U7.109 | length 4436.9
  Top Layer w8: R31.1@1400,1557.4 1340,1617.4 1340,1780 1110,2010 1110,2120 JP2.4@1060,2170 1060,2240 1160,2340 1160,2820 880,3100 880,4280 1150,4550 1550,4550 v1(1570,4530) ; U7.109@1473.36,4223.2 1586.8,4223.2 1620,4190 v1(1680,4190)
  Bottom Layer w8: v1(1570,4530) 1640,4460 1640,4280 1680,4240 v1(1680,4190)
MPA3: JP2.5 R41.1 U7.108 | length 4016.4
  Top Layer w8: R41.1@1400,1737.4 1400,1780 1160,2020 JP2.5@1160,2070 1160,2110 1110,2160 1110,2250 1180,2320 1180,2830 900,3110 900,4270 1160,4530 1470,4530 v1(1490,4510) ; U7.108@1473.36,4242.89 1617.11,4242.89 v1(1620,4240)
  Bottom Layer w8: v1(1490,4510) 1520,4480 1590,4480 1620,4450 v1(1620,4240)
MPA4: JP2.6 R32.1 U7.102 | length 3862.6
  Top Layer w8: R32.1@1500,1550 R32.1@1500,1557.4 ; R32.1@1500,1560 R32.1@1500,1557.4 ; U7.102@1597.38,4386.59 1597.38,4462.62 1583.58,4476.42 1473.58,4476.42 1440,4510 1170,4510 920,4260 920,3120 1200,2840 1200,2300 1160,2260 JP2.6@1160,2170 1210,2120 1210,2020 1450,1780 1450,1635.22 1480,1605.22 1480,1577.4 R32.1@1500,1557.4
MPA5: JP2.7 R42.1 U7.101 | length 3668.8
  Top Layer w8: R42.1@1500,1737.4 1500,1790 1260,2030 JP2.7@1260,2070 1260,2110 1210,2160 1210,2250 1220,2260 1220,2850 940,3130 940,4250 1180,4490 1355.25,4490 1473.25,4372 1508,4372 1568,4312 1602,4312 1617.06,4327.06 U7.101@1617.06,4386.59
MPA6: JP2.8 R33.1 U7.100 | length 3870.2
  Top Layer w8: R33.1@1600,1557.4 1580,1577.4 1580,1605.22 1550,1635.22 1550,1790 1310,2030 1310,2120 JP2.8@1260,2170 1260,2460 1240,2480 1240,2860 960,3140 960,4240 1190,4470 1352.63,4470 1466.63,4356 1501.37,4356 1561.37,4296 1616,4296 1636.75,4316.75 U7.100@1636.75,4386.59
MPA7: JP2.9 R43.1 U7.99 | length 3678.5
  Top Layer w8: R43.1@1600,1737.4 1600,1780 1360,2020 JP2.9@1360,2070 1360,2110 1310,2160 1310,2440 1260,2490 1260,2870 980,3150 980,4230 1200,4450 1350,4450 1460,4340 1494.75,4340 1554.75,4280 1630,4280 1656.43,4306.43 U7.99@1656.43,4386.59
